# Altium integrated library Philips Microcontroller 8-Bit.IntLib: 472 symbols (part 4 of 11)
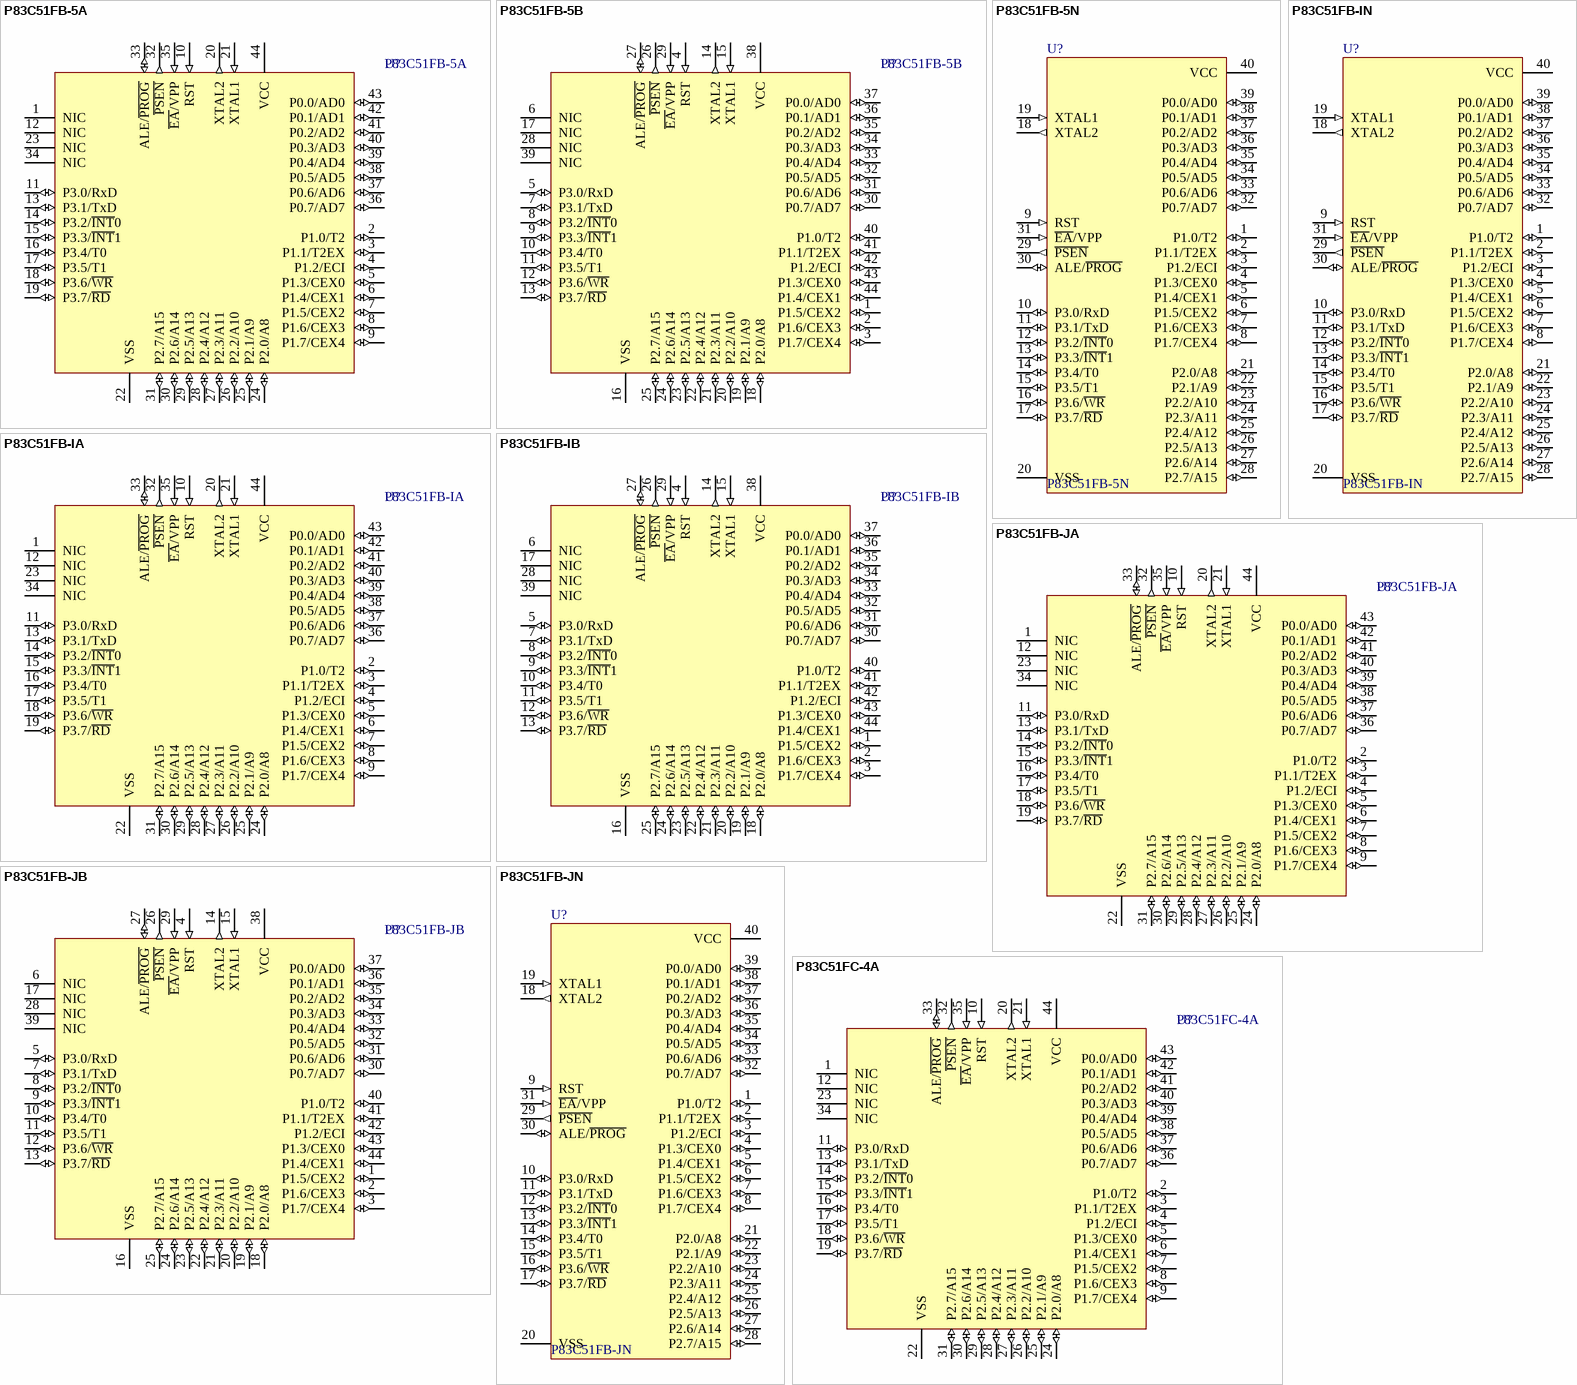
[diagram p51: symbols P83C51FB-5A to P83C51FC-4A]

## P83C51FB-JA
designator U?
80C51 8-Bit Microcontroller Family: 256 B RAM, 16 kB ROM, 5V, Low Power, High Speed
footprint SOT187-2_N (Leaded Chip Carrier, 44-Leads, Body 16.6x16.6mm, Pitch 1.27mm, IPC Medium Density)
footprint SOT187-2_L (Leaded Chip Carrier, 44-Leads, Body 16.6x16.6mm, Pitch 1.27mm, IPC High Density)
footprint SOT187-2_M (Leaded Chip Carrier, 44-Leads, Body 16.6x16.6mm, Pitch 1.27mm, IPC Low Density)
pins: 1 NIC, 2 P1.0/T2 (io), 3 P1.1/T2EX (io), 4 P1.2/ECI (io), 5 P1.3/CEX0 (io), 6 P1.4/CEX1 (io), 7 P1.5/CEX2 (io), 8 P1.6/CEX3 (io), 9 P1.7/CEX4 (io), 10 RST (in), 11 P3.0/RxD (io), 12 NIC, 13 P3.1/TxD (io), 14 P3.2/~{INT}0 (io), 15 P3.3/~{INT}1 (io), 16 P3.4/T0 (io), 17 P3.5/T1 (io), 18 P3.6/~{WR} (io), 19 P3.7/~{RD} (io), 20 XTAL2 (out), 21 XTAL1 (in), 22 VSS (power), 23 NIC, 24 P2.0/A8 (io), 25 P2.1/A9 (io), 26 P2.2/A10 (io), 27 P2.3/A11 (io), 28 P2.4/A12 (io), 29 P2.5/A13 (io), 30 P2.6/A14 (io), 31 P2.7/A15 (io), 32 ~{PSEN} (out), 33 ALE/~{PROG} (io), 34 NIC, 35 ~{EA}/VPP (in), 36 P0.7/AD7 (io), 37 P0.6/AD6 (io), 38 P0.5/AD5 (io), 39 P0.4/AD4 (io), 40 P0.3/AD3 (io), 41 P0.2/AD2 (io), 42 P0.1/AD1 (io), 43 P0.0/AD0 (io), 44 VCC (power)

## P83C51FB-JB
designator U?
80C51 8-Bit Microcontroller Family: 256 B RAM, 16 kB ROM, 5V, Low Power, High Speed
footprint SOT307-2_N (QFP, 44-Leads, Body 10x10mm, Pitch 0.8mm, IPC Medium Density)
footprint SOT307-2_L (QFP, 44-Leads, Body 10x10mm, Pitch 0.8mm, IPC High Density)
footprint SOT307-2_M (QFP, 44-Leads, Body 10x10mm, Pitch 0.8mm, IPC Low Density)
pins: 1 P1.5/CEX2 (io), 2 P1.6/CEX3 (io), 3 P1.7/CEX4 (io), 4 RST (in), 5 P3.0/RxD (io), 6 NIC, 7 P3.1/TxD (io), 8 P3.2/~{INT}0 (io), 9 P3.3/~{INT}1 (io), 10 P3.4/T0 (io), 11 P3.5/T1 (io), 12 P3.6/~{WR} (io), 13 P3.7/~{RD} (io), 14 XTAL2 (out), 15 XTAL1 (in), 16 VSS (power), 17 NIC, 18 P2.0/A8 (io), 19 P2.1/A9 (io), 20 P2.2/A10 (io), 21 P2.3/A11 (io), 22 P2.4/A12 (io), 23 P2.5/A13 (io), 24 P2.6/A14 (io), 25 P2.7/A15 (io), 26 ~{PSEN} (out), 27 ALE/~{PROG} (io), 28 NIC, 29 ~{EA}/VPP (in), 30 P0.7/AD7 (io), 31 P0.6/AD6 (io), 32 P0.5/AD5 (io), 33 P0.4/AD4 (io), 34 P0.3/AD3 (io), 35 P0.2/AD2 (io), 36 P0.1/AD1 (io), 37 P0.0/AD0 (io), 38 VCC (power), 39 NIC, 40 P1.0/T2 (io), 41 P1.1/T2EX (io), 42 P1.2/ECI (io), 43 P1.3/CEX0 (io), 44 P1.4/CEX1 (io)

## P83C51FB-JN
designator U?
80C51 8-Bit Microcontroller Family: 256 B RAM, 16 kB ROM, 5V, Low Power, High Speed
footprint SOT129-1 (DIP, Plastic; 40 Leads; Row Spacing 15.24 mm; Pitch 2.54 mm)
pins: 1 P1.0/T2 (io), 2 P1.1/T2EX (io), 3 P1.2/ECI (io), 4 P1.3/CEX0 (io), 5 P1.4/CEX1 (io), 6 P1.5/CEX2 (io), 7 P1.6/CEX3 (io), 8 P1.7/CEX4 (io), 9 RST (in), 10 P3.0/RxD (io), 11 P3.1/TxD (io), 12 P3.2/~{INT}0 (io), 13 P3.3/~{INT}1 (io), 14 P3.4/T0 (io), 15 P3.5/T1 (io), 16 P3.6/~{WR} (io), 17 P3.7/~{RD} (io), 18 XTAL2 (out), 19 XTAL1 (in), 20 VSS (power), 21 P2.0/A8 (io), 22 P2.1/A9 (io), 23 P2.2/A10 (io), 24 P2.3/A11 (io), 25 P2.4/A12 (io), 26 P2.5/A13 (io), 27 P2.6/A14 (io), 28 P2.7/A15 (io), 29 ~{PSEN} (out), 30 ALE/~{PROG} (io), 31 ~{EA}/VPP (in), 32 P0.7/AD7 (io), 33 P0.6/AD6 (io), 34 P0.5/AD5 (io), 35 P0.4/AD4 (io), 36 P0.3/AD3 (io), 37 P0.2/AD2 (io), 38 P0.1/AD1 (io), 39 P0.0/AD0 (io), 40 VCC (power)

## P83C51FC-4A
designator U?
80C51 8-Bit Microcontroller Family: 256 B RAM, 32 kB ROM, 2.7V-5.5V, Low Power, High Speed
footprint SOT187-2_N (Leaded Chip Carrier, 44-Leads, Body 16.6x16.6mm, Pitch 1.27mm, IPC Medium Density)
footprint SOT187-2_L (Leaded Chip Carrier, 44-Leads, Body 16.6x16.6mm, Pitch 1.27mm, IPC High Density)
footprint SOT187-2_M (Leaded Chip Carrier, 44-Leads, Body 16.6x16.6mm, Pitch 1.27mm, IPC Low Density)
pins: 1 NIC, 2 P1.0/T2 (io), 3 P1.1/T2EX (io), 4 P1.2/ECI (io), 5 P1.3/CEX0 (io), 6 P1.4/CEX1 (io), 7 P1.5/CEX2 (io), 8 P1.6/CEX3 (io), 9 P1.7/CEX4 (io), 10 RST (in), 11 P3.0/RxD (io), 12 NIC, 13 P3.1/TxD (io), 14 P3.2/~{INT}0 (io), 15 P3.3/~{INT}1 (io), 16 P3.4/T0 (io), 17 P3.5/T1 (io), 18 P3.6/~{WR} (io), 19 P3.7/~{RD} (io), 20 XTAL2 (out), 21 XTAL1 (in), 22 VSS (power), 23 NIC, 24 P2.0/A8 (io), 25 P2.1/A9 (io), 26 P2.2/A10 (io), 27 P2.3/A11 (io), 28 P2.4/A12 (io), 29 P2.5/A13 (io), 30 P2.6/A14 (io), 31 P2.7/A15 (io), 32 ~{PSEN} (out), 33 ALE/~{PROG} (io), 34 NIC, 35 ~{EA}/VPP (in), 36 P0.7/AD7 (io), 37 P0.6/AD6 (io), 38 P0.5/AD5 (io), 39 P0.4/AD4 (io), 40 P0.3/AD3 (io), 41 P0.2/AD2 (io), 42 P0.1/AD1 (io), 43 P0.0/AD0 (io), 44 VCC (power)

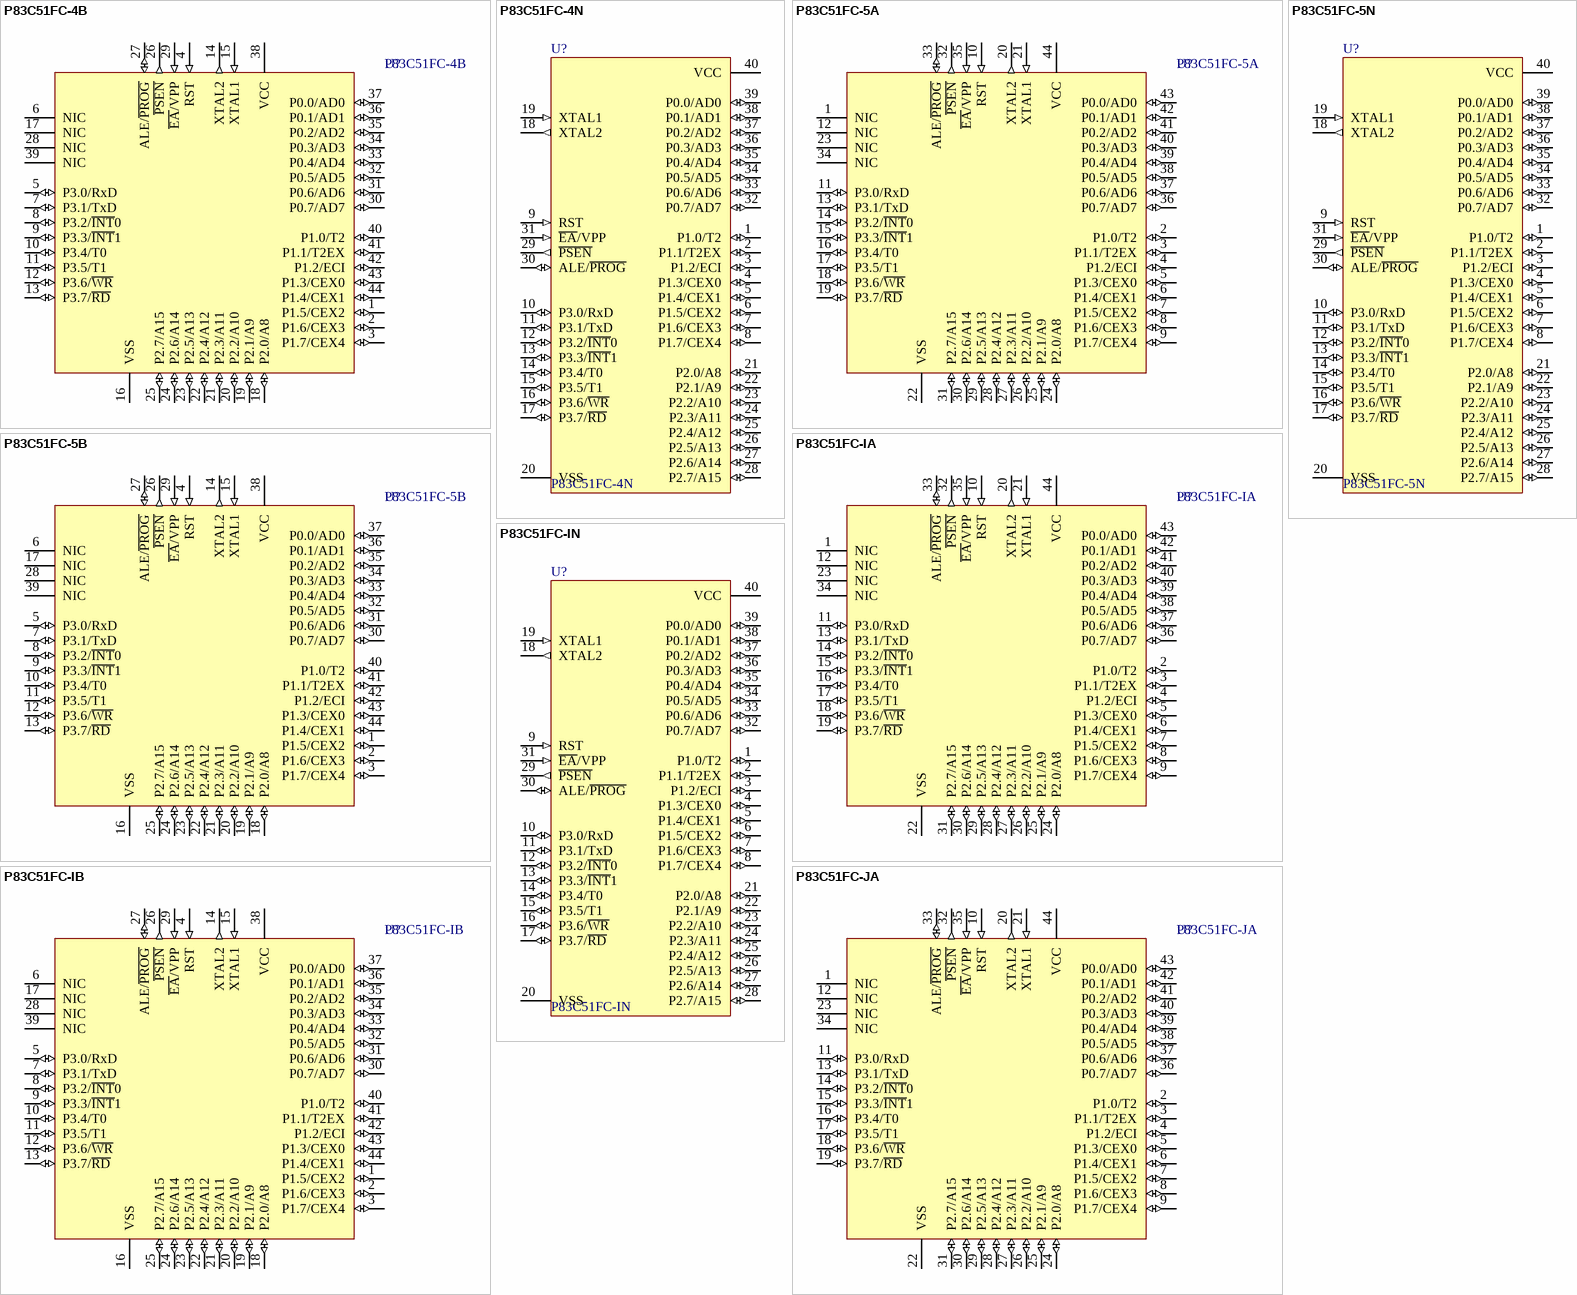
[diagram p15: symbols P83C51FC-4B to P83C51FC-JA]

## P83C51FC-4B
designator U?
80C51 8-Bit Microcontroller Family: 256 B RAM, 32 kB ROM, 2.7V-5.5V, Low Power, High Speed
footprint SOT307-2_N (QFP, 44-Leads, Body 10x10mm, Pitch 0.8mm, IPC Medium Density)
footprint SOT307-2_L (QFP, 44-Leads, Body 10x10mm, Pitch 0.8mm, IPC High Density)
footprint SOT307-2_M (QFP, 44-Leads, Body 10x10mm, Pitch 0.8mm, IPC Low Density)
pins: 1 P1.5/CEX2 (io), 2 P1.6/CEX3 (io), 3 P1.7/CEX4 (io), 4 RST (in), 5 P3.0/RxD (io), 6 NIC, 7 P3.1/TxD (io), 8 P3.2/~{INT}0 (io), 9 P3.3/~{INT}1 (io), 10 P3.4/T0 (io), 11 P3.5/T1 (io), 12 P3.6/~{WR} (io), 13 P3.7/~{RD} (io), 14 XTAL2 (out), 15 XTAL1 (in), 16 VSS (power), 17 NIC, 18 P2.0/A8 (io), 19 P2.1/A9 (io), 20 P2.2/A10 (io), 21 P2.3/A11 (io), 22 P2.4/A12 (io), 23 P2.5/A13 (io), 24 P2.6/A14 (io), 25 P2.7/A15 (io), 26 ~{PSEN} (out), 27 ALE/~{PROG} (io), 28 NIC, 29 ~{EA}/VPP (in), 30 P0.7/AD7 (io), 31 P0.6/AD6 (io), 32 P0.5/AD5 (io), 33 P0.4/AD4 (io), 34 P0.3/AD3 (io), 35 P0.2/AD2 (io), 36 P0.1/AD1 (io), 37 P0.0/AD0 (io), 38 VCC (power), 39 NIC, 40 P1.0/T2 (io), 41 P1.1/T2EX (io), 42 P1.2/ECI (io), 43 P1.3/CEX0 (io), 44 P1.4/CEX1 (io)

## P83C51FC-4N
designator U?
80C51 8-Bit Microcontroller Family: 256 B RAM, 32 kB ROM, 2.7V-5.5V, Low Power, High Speed
footprint SOT129-1 (DIP, Plastic; 40 Leads; Row Spacing 15.24 mm; Pitch 2.54 mm)
pins: 1 P1.0/T2 (io), 2 P1.1/T2EX (io), 3 P1.2/ECI (io), 4 P1.3/CEX0 (io), 5 P1.4/CEX1 (io), 6 P1.5/CEX2 (io), 7 P1.6/CEX3 (io), 8 P1.7/CEX4 (io), 9 RST (in), 10 P3.0/RxD (io), 11 P3.1/TxD (io), 12 P3.2/~{INT}0 (io), 13 P3.3/~{INT}1 (io), 14 P3.4/T0 (io), 15 P3.5/T1 (io), 16 P3.6/~{WR} (io), 17 P3.7/~{RD} (io), 18 XTAL2 (out), 19 XTAL1 (in), 20 VSS (power), 21 P2.0/A8 (io), 22 P2.1/A9 (io), 23 P2.2/A10 (io), 24 P2.3/A11 (io), 25 P2.4/A12 (io), 26 P2.5/A13 (io), 27 P2.6/A14 (io), 28 P2.7/A15 (io), 29 ~{PSEN} (out), 30 ALE/~{PROG} (io), 31 ~{EA}/VPP (in), 32 P0.7/AD7 (io), 33 P0.6/AD6 (io), 34 P0.5/AD5 (io), 35 P0.4/AD4 (io), 36 P0.3/AD3 (io), 37 P0.2/AD2 (io), 38 P0.1/AD1 (io), 39 P0.0/AD0 (io), 40 VCC (power)

## P83C51FC-5A
designator U?
80C51 8-Bit Microcontroller Family: 256 B RAM, 32 kB ROM, 2.7V-5.5V, Low Power, High Speed
footprint SOT187-2_N (Leaded Chip Carrier, 44-Leads, Body 16.6x16.6mm, Pitch 1.27mm, IPC Medium Density)
footprint SOT187-2_L (Leaded Chip Carrier, 44-Leads, Body 16.6x16.6mm, Pitch 1.27mm, IPC High Density)
footprint SOT187-2_M (Leaded Chip Carrier, 44-Leads, Body 16.6x16.6mm, Pitch 1.27mm, IPC Low Density)
pins: 1 NIC, 2 P1.0/T2 (io), 3 P1.1/T2EX (io), 4 P1.2/ECI (io), 5 P1.3/CEX0 (io), 6 P1.4/CEX1 (io), 7 P1.5/CEX2 (io), 8 P1.6/CEX3 (io), 9 P1.7/CEX4 (io), 10 RST (in), 11 P3.0/RxD (io), 12 NIC, 13 P3.1/TxD (io), 14 P3.2/~{INT}0 (io), 15 P3.3/~{INT}1 (io), 16 P3.4/T0 (io), 17 P3.5/T1 (io), 18 P3.6/~{WR} (io), 19 P3.7/~{RD} (io), 20 XTAL2 (out), 21 XTAL1 (in), 22 VSS (power), 23 NIC, 24 P2.0/A8 (io), 25 P2.1/A9 (io), 26 P2.2/A10 (io), 27 P2.3/A11 (io), 28 P2.4/A12 (io), 29 P2.5/A13 (io), 30 P2.6/A14 (io), 31 P2.7/A15 (io), 32 ~{PSEN} (out), 33 ALE/~{PROG} (io), 34 NIC, 35 ~{EA}/VPP (in), 36 P0.7/AD7 (io), 37 P0.6/AD6 (io), 38 P0.5/AD5 (io), 39 P0.4/AD4 (io), 40 P0.3/AD3 (io), 41 P0.2/AD2 (io), 42 P0.1/AD1 (io), 43 P0.0/AD0 (io), 44 VCC (power)

## P83C51FC-5B
designator U?
80C51 8-Bit Microcontroller Family: 256 B RAM, 32 kB ROM, 2.7V-5.5V, Low Power, High Speed
footprint SOT307-2_N (QFP, 44-Leads, Body 10x10mm, Pitch 0.8mm, IPC Medium Density)
footprint SOT307-2_L (QFP, 44-Leads, Body 10x10mm, Pitch 0.8mm, IPC High Density)
footprint SOT307-2_M (QFP, 44-Leads, Body 10x10mm, Pitch 0.8mm, IPC Low Density)
pins: 1 P1.5/CEX2 (io), 2 P1.6/CEX3 (io), 3 P1.7/CEX4 (io), 4 RST (in), 5 P3.0/RxD (io), 6 NIC, 7 P3.1/TxD (io), 8 P3.2/~{INT}0 (io), 9 P3.3/~{INT}1 (io), 10 P3.4/T0 (io), 11 P3.5/T1 (io), 12 P3.6/~{WR} (io), 13 P3.7/~{RD} (io), 14 XTAL2 (out), 15 XTAL1 (in), 16 VSS (power), 17 NIC, 18 P2.0/A8 (io), 19 P2.1/A9 (io), 20 P2.2/A10 (io), 21 P2.3/A11 (io), 22 P2.4/A12 (io), 23 P2.5/A13 (io), 24 P2.6/A14 (io), 25 P2.7/A15 (io), 26 ~{PSEN} (out), 27 ALE/~{PROG} (io), 28 NIC, 29 ~{EA}/VPP (in), 30 P0.7/AD7 (io), 31 P0.6/AD6 (io), 32 P0.5/AD5 (io), 33 P0.4/AD4 (io), 34 P0.3/AD3 (io), 35 P0.2/AD2 (io), 36 P0.1/AD1 (io), 37 P0.0/AD0 (io), 38 VCC (power), 39 NIC, 40 P1.0/T2 (io), 41 P1.1/T2EX (io), 42 P1.2/ECI (io), 43 P1.3/CEX0 (io), 44 P1.4/CEX1 (io)

## P83C51FC-5N
designator U?
80C51 8-Bit Microcontroller Family: 256 B RAM, 32 kB ROM, 2.7V-5.5V, Low Power, High Speed
footprint SOT129-1 (DIP, Plastic; 40 Leads; Row Spacing 15.24 mm; Pitch 2.54 mm)
pins: 1 P1.0/T2 (io), 2 P1.1/T2EX (io), 3 P1.2/ECI (io), 4 P1.3/CEX0 (io), 5 P1.4/CEX1 (io), 6 P1.5/CEX2 (io), 7 P1.6/CEX3 (io), 8 P1.7/CEX4 (io), 9 RST (in), 10 P3.0/RxD (io), 11 P3.1/TxD (io), 12 P3.2/~{INT}0 (io), 13 P3.3/~{INT}1 (io), 14 P3.4/T0 (io), 15 P3.5/T1 (io), 16 P3.6/~{WR} (io), 17 P3.7/~{RD} (io), 18 XTAL2 (out), 19 XTAL1 (in), 20 VSS (power), 21 P2.0/A8 (io), 22 P2.1/A9 (io), 23 P2.2/A10 (io), 24 P2.3/A11 (io), 25 P2.4/A12 (io), 26 P2.5/A13 (io), 27 P2.6/A14 (io), 28 P2.7/A15 (io), 29 ~{PSEN} (out), 30 ALE/~{PROG} (io), 31 ~{EA}/VPP (in), 32 P0.7/AD7 (io), 33 P0.6/AD6 (io), 34 P0.5/AD5 (io), 35 P0.4/AD4 (io), 36 P0.3/AD3 (io), 37 P0.2/AD2 (io), 38 P0.1/AD1 (io), 39 P0.0/AD0 (io), 40 VCC (power)

## P83C51FC-IA
designator U?
80C51 8-Bit Microcontroller Family: 256 B RAM, 32 kB ROM, 5V, Low Power, High Speed
footprint SOT187-2_N (Leaded Chip Carrier, 44-Leads, Body 16.6x16.6mm, Pitch 1.27mm, IPC Medium Density)
footprint SOT187-2_L (Leaded Chip Carrier, 44-Leads, Body 16.6x16.6mm, Pitch 1.27mm, IPC High Density)
footprint SOT187-2_M (Leaded Chip Carrier, 44-Leads, Body 16.6x16.6mm, Pitch 1.27mm, IPC Low Density)
pins: 1 NIC, 2 P1.0/T2 (io), 3 P1.1/T2EX (io), 4 P1.2/ECI (io), 5 P1.3/CEX0 (io), 6 P1.4/CEX1 (io), 7 P1.5/CEX2 (io), 8 P1.6/CEX3 (io), 9 P1.7/CEX4 (io), 10 RST (in), 11 P3.0/RxD (io), 12 NIC, 13 P3.1/TxD (io), 14 P3.2/~{INT}0 (io), 15 P3.3/~{INT}1 (io), 16 P3.4/T0 (io), 17 P3.5/T1 (io), 18 P3.6/~{WR} (io), 19 P3.7/~{RD} (io), 20 XTAL2 (out), 21 XTAL1 (in), 22 VSS (power), 23 NIC, 24 P2.0/A8 (io), 25 P2.1/A9 (io), 26 P2.2/A10 (io), 27 P2.3/A11 (io), 28 P2.4/A12 (io), 29 P2.5/A13 (io), 30 P2.6/A14 (io), 31 P2.7/A15 (io), 32 ~{PSEN} (out), 33 ALE/~{PROG} (io), 34 NIC, 35 ~{EA}/VPP (in), 36 P0.7/AD7 (io), 37 P0.6/AD6 (io), 38 P0.5/AD5 (io), 39 P0.4/AD4 (io), 40 P0.3/AD3 (io), 41 P0.2/AD2 (io), 42 P0.1/AD1 (io), 43 P0.0/AD0 (io), 44 VCC (power)

## P83C51FC-IB
designator U?
80C51 8-Bit Microcontroller Family: 256 B RAM, 32 kB ROM, 5V, Low Power, High Speed
footprint SOT307-2_N (QFP, 44-Leads, Body 10x10mm, Pitch 0.8mm, IPC Medium Density)
footprint SOT307-2_L (QFP, 44-Leads, Body 10x10mm, Pitch 0.8mm, IPC High Density)
footprint SOT307-2_M (QFP, 44-Leads, Body 10x10mm, Pitch 0.8mm, IPC Low Density)
pins: 1 P1.5/CEX2 (io), 2 P1.6/CEX3 (io), 3 P1.7/CEX4 (io), 4 RST (in), 5 P3.0/RxD (io), 6 NIC, 7 P3.1/TxD (io), 8 P3.2/~{INT}0 (io), 9 P3.3/~{INT}1 (io), 10 P3.4/T0 (io), 11 P3.5/T1 (io), 12 P3.6/~{WR} (io), 13 P3.7/~{RD} (io), 14 XTAL2 (out), 15 XTAL1 (in), 16 VSS (power), 17 NIC, 18 P2.0/A8 (io), 19 P2.1/A9 (io), 20 P2.2/A10 (io), 21 P2.3/A11 (io), 22 P2.4/A12 (io), 23 P2.5/A13 (io), 24 P2.6/A14 (io), 25 P2.7/A15 (io), 26 ~{PSEN} (out), 27 ALE/~{PROG} (io), 28 NIC, 29 ~{EA}/VPP (in), 30 P0.7/AD7 (io), 31 P0.6/AD6 (io), 32 P0.5/AD5 (io), 33 P0.4/AD4 (io), 34 P0.3/AD3 (io), 35 P0.2/AD2 (io), 36 P0.1/AD1 (io), 37 P0.0/AD0 (io), 38 VCC (power), 39 NIC, 40 P1.0/T2 (io), 41 P1.1/T2EX (io), 42 P1.2/ECI (io), 43 P1.3/CEX0 (io), 44 P1.4/CEX1 (io)

## P83C51FC-IN
designator U?
80C51 8-Bit Microcontroller Family: 256 B RAM, 32 kB ROM, 5V, Low Power, High Speed
footprint SOT129-1 (DIP, Plastic; 40 Leads; Row Spacing 15.24 mm; Pitch 2.54 mm)
pins: 1 P1.0/T2 (io), 2 P1.1/T2EX (io), 3 P1.2/ECI (io), 4 P1.3/CEX0 (io), 5 P1.4/CEX1 (io), 6 P1.5/CEX2 (io), 7 P1.6/CEX3 (io), 8 P1.7/CEX4 (io), 9 RST (in), 10 P3.0/RxD (io), 11 P3.1/TxD (io), 12 P3.2/~{INT}0 (io), 13 P3.3/~{INT}1 (io), 14 P3.4/T0 (io), 15 P3.5/T1 (io), 16 P3.6/~{WR} (io), 17 P3.7/~{RD} (io), 18 XTAL2 (out), 19 XTAL1 (in), 20 VSS (power), 21 P2.0/A8 (io), 22 P2.1/A9 (io), 23 P2.2/A10 (io), 24 P2.3/A11 (io), 25 P2.4/A12 (io), 26 P2.5/A13 (io), 27 P2.6/A14 (io), 28 P2.7/A15 (io), 29 ~{PSEN} (out), 30 ALE/~{PROG} (io), 31 ~{EA}/VPP (in), 32 P0.7/AD7 (io), 33 P0.6/AD6 (io), 34 P0.5/AD5 (io), 35 P0.4/AD4 (io), 36 P0.3/AD3 (io), 37 P0.2/AD2 (io), 38 P0.1/AD1 (io), 39 P0.0/AD0 (io), 40 VCC (power)

## P83C51FC-JA
designator U?
80C51 8-Bit Microcontroller Family: 256 B RAM, 32 kB ROM, 5V, Low Power, High Speed
footprint SOT187-2_N (Leaded Chip Carrier, 44-Leads, Body 16.6x16.6mm, Pitch 1.27mm, IPC Medium Density)
footprint SOT187-2_L (Leaded Chip Carrier, 44-Leads, Body 16.6x16.6mm, Pitch 1.27mm, IPC High Density)
footprint SOT187-2_M (Leaded Chip Carrier, 44-Leads, Body 16.6x16.6mm, Pitch 1.27mm, IPC Low Density)
pins: 1 NIC, 2 P1.0/T2 (io), 3 P1.1/T2EX (io), 4 P1.2/ECI (io), 5 P1.3/CEX0 (io), 6 P1.4/CEX1 (io), 7 P1.5/CEX2 (io), 8 P1.6/CEX3 (io), 9 P1.7/CEX4 (io), 10 RST (in), 11 P3.0/RxD (io), 12 NIC, 13 P3.1/TxD (io), 14 P3.2/~{INT}0 (io), 15 P3.3/~{INT}1 (io), 16 P3.4/T0 (io), 17 P3.5/T1 (io), 18 P3.6/~{WR} (io), 19 P3.7/~{RD} (io), 20 XTAL2 (out), 21 XTAL1 (in), 22 VSS (power), 23 NIC, 24 P2.0/A8 (io), 25 P2.1/A9 (io), 26 P2.2/A10 (io), 27 P2.3/A11 (io), 28 P2.4/A12 (io), 29 P2.5/A13 (io), 30 P2.6/A14 (io), 31 P2.7/A15 (io), 32 ~{PSEN} (out), 33 ALE/~{PROG} (io), 34 NIC, 35 ~{EA}/VPP (in), 36 P0.7/AD7 (io), 37 P0.6/AD6 (io), 38 P0.5/AD5 (io), 39 P0.4/AD4 (io), 40 P0.3/AD3 (io), 41 P0.2/AD2 (io), 42 P0.1/AD1 (io), 43 P0.0/AD0 (io), 44 VCC (power)

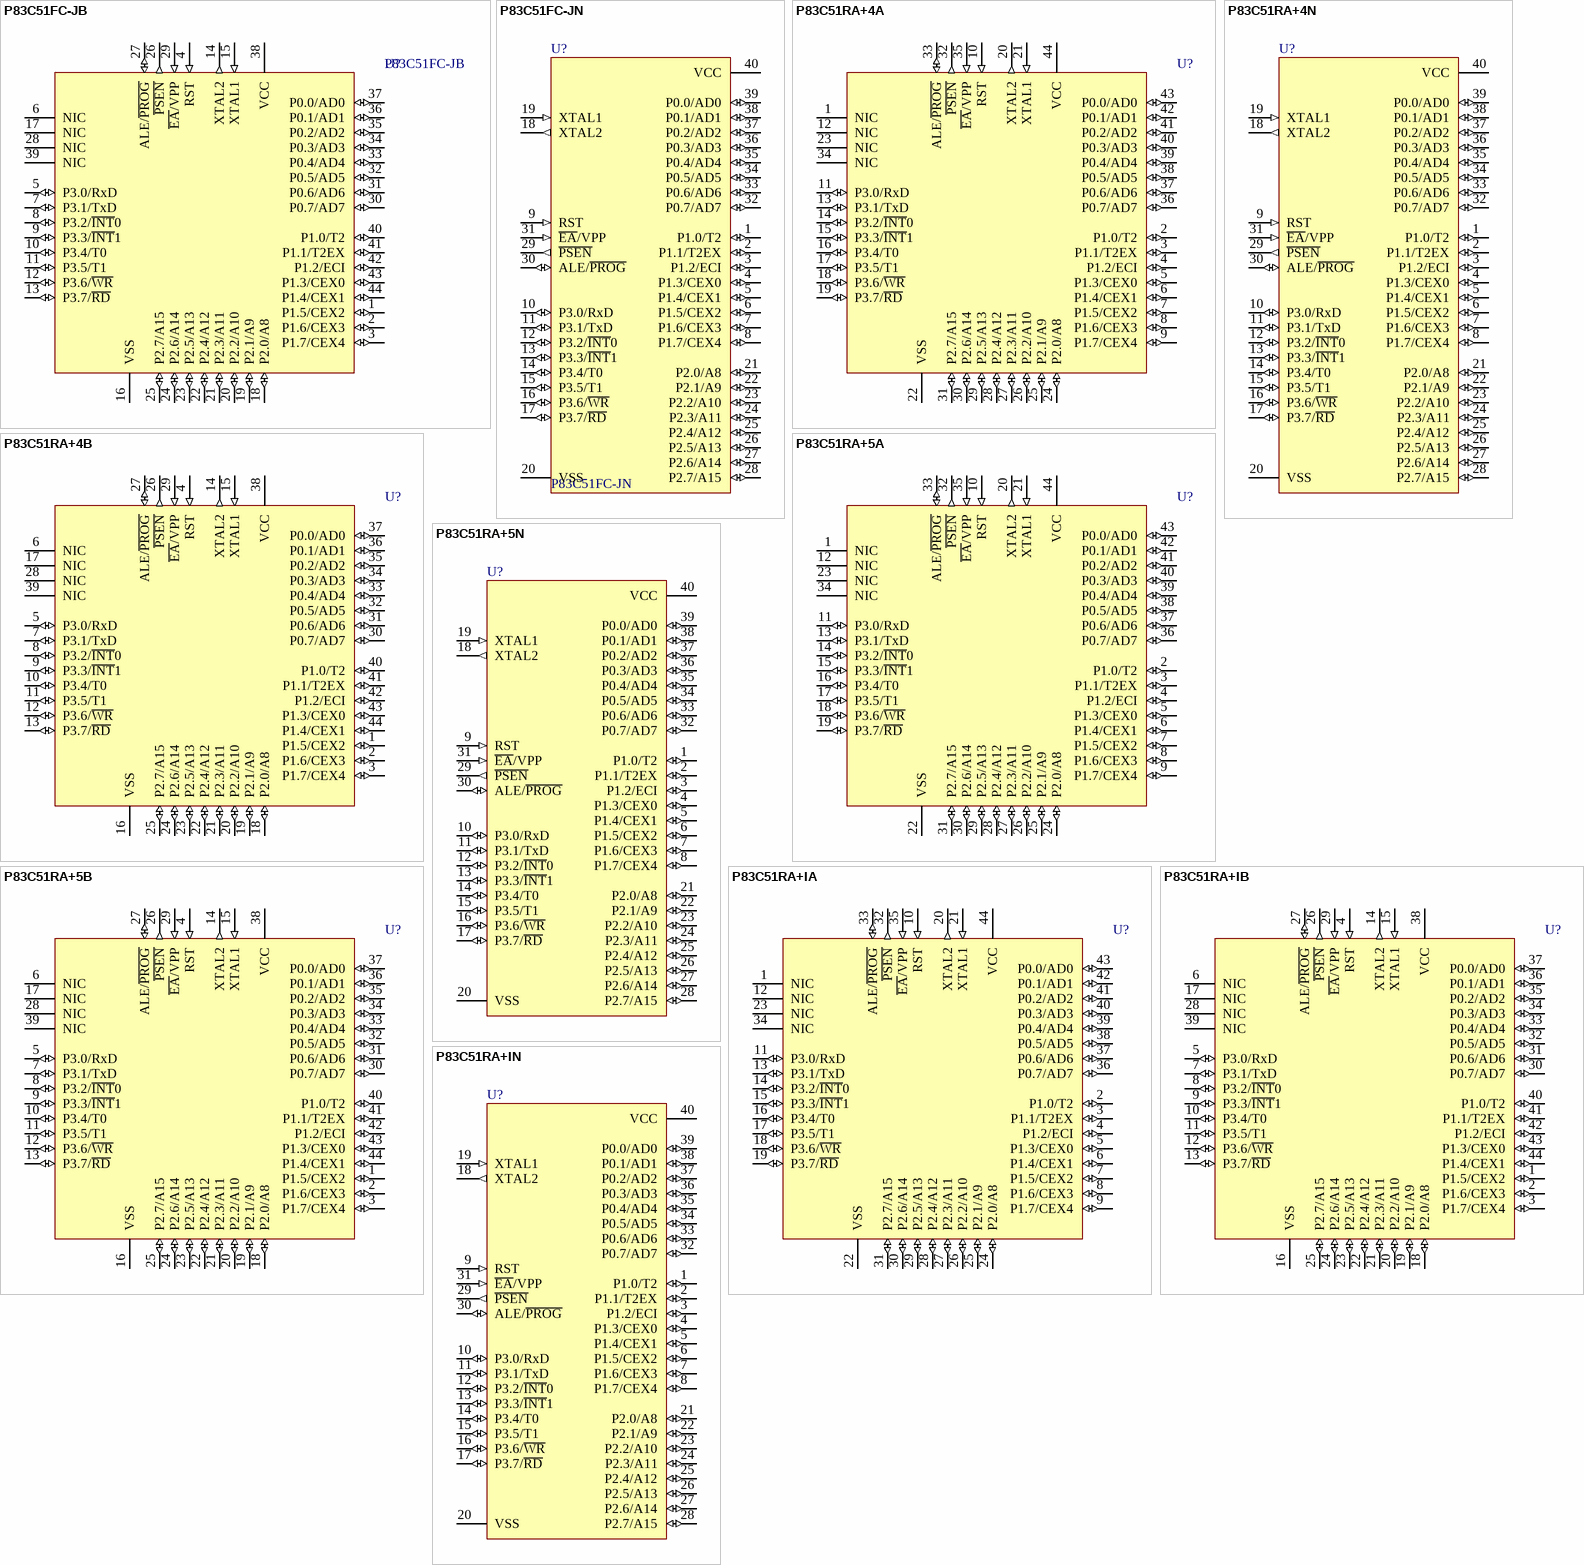
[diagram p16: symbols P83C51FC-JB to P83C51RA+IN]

## P83C51FC-JB
designator U?
80C51 8-Bit Microcontroller Family: 256 B RAM, 32 kB ROM, 5V, Low Power, High Speed
footprint SOT307-2_N (QFP, 44-Leads, Body 10x10mm, Pitch 0.8mm, IPC Medium Density)
footprint SOT307-2_L (QFP, 44-Leads, Body 10x10mm, Pitch 0.8mm, IPC High Density)
footprint SOT307-2_M (QFP, 44-Leads, Body 10x10mm, Pitch 0.8mm, IPC Low Density)
pins: 1 P1.5/CEX2 (io), 2 P1.6/CEX3 (io), 3 P1.7/CEX4 (io), 4 RST (in), 5 P3.0/RxD (io), 6 NIC, 7 P3.1/TxD (io), 8 P3.2/~{INT}0 (io), 9 P3.3/~{INT}1 (io), 10 P3.4/T0 (io), 11 P3.5/T1 (io), 12 P3.6/~{WR} (io), 13 P3.7/~{RD} (io), 14 XTAL2 (out), 15 XTAL1 (in), 16 VSS (power), 17 NIC, 18 P2.0/A8 (io), 19 P2.1/A9 (io), 20 P2.2/A10 (io), 21 P2.3/A11 (io), 22 P2.4/A12 (io), 23 P2.5/A13 (io), 24 P2.6/A14 (io), 25 P2.7/A15 (io), 26 ~{PSEN} (out), 27 ALE/~{PROG} (io), 28 NIC, 29 ~{EA}/VPP (in), 30 P0.7/AD7 (io), 31 P0.6/AD6 (io), 32 P0.5/AD5 (io), 33 P0.4/AD4 (io), 34 P0.3/AD3 (io), 35 P0.2/AD2 (io), 36 P0.1/AD1 (io), 37 P0.0/AD0 (io), 38 VCC (power), 39 NIC, 40 P1.0/T2 (io), 41 P1.1/T2EX (io), 42 P1.2/ECI (io), 43 P1.3/CEX0 (io), 44 P1.4/CEX1 (io)

## P83C51FC-JN
designator U?
80C51 8-Bit Microcontroller Family: 256 B RAM, 32 kB ROM, 5V, Low Power, High Speed
footprint SOT129-1 (DIP, Plastic; 40 Leads; Row Spacing 15.24 mm; Pitch 2.54 mm)
pins: 1 P1.0/T2 (io), 2 P1.1/T2EX (io), 3 P1.2/ECI (io), 4 P1.3/CEX0 (io), 5 P1.4/CEX1 (io), 6 P1.5/CEX2 (io), 7 P1.6/CEX3 (io), 8 P1.7/CEX4 (io), 9 RST (in), 10 P3.0/RxD (io), 11 P3.1/TxD (io), 12 P3.2/~{INT}0 (io), 13 P3.3/~{INT}1 (io), 14 P3.4/T0 (io), 15 P3.5/T1 (io), 16 P3.6/~{WR} (io), 17 P3.7/~{RD} (io), 18 XTAL2 (out), 19 XTAL1 (in), 20 VSS (power), 21 P2.0/A8 (io), 22 P2.1/A9 (io), 23 P2.2/A10 (io), 24 P2.3/A11 (io), 25 P2.4/A12 (io), 26 P2.5/A13 (io), 27 P2.6/A14 (io), 28 P2.7/A15 (io), 29 ~{PSEN} (out), 30 ALE/~{PROG} (io), 31 ~{EA}/VPP (in), 32 P0.7/AD7 (io), 33 P0.6/AD6 (io), 34 P0.5/AD5 (io), 35 P0.4/AD4 (io), 36 P0.3/AD3 (io), 37 P0.2/AD2 (io), 38 P0.1/AD1 (io), 39 P0.0/AD0 (io), 40 VCC (power)

## P83C51RA+4A
designator U?
80C51 8-Bit Microcontroller Family: 512 B RAM, 8 kB ROM, 2.7V-5.5V, Low Power, High Speed
footprint SOT187-2_N (Leaded Chip Carrier, 44-Leads, Body 16.6x16.6mm, Pitch 1.27mm, IPC Medium Density)
footprint SOT187-2_L (Leaded Chip Carrier, 44-Leads, Body 16.6x16.6mm, Pitch 1.27mm, IPC High Density)
footprint SOT187-2_M (Leaded Chip Carrier, 44-Leads, Body 16.6x16.6mm, Pitch 1.27mm, IPC Low Density)
pins: 1 NIC, 2 P1.0/T2 (io), 3 P1.1/T2EX (io), 4 P1.2/ECI (io), 5 P1.3/CEX0 (io), 6 P1.4/CEX1 (io), 7 P1.5/CEX2 (io), 8 P1.6/CEX3 (io), 9 P1.7/CEX4 (io), 10 RST (in), 11 P3.0/RxD (io), 12 NIC, 13 P3.1/TxD (io), 14 P3.2/~{INT}0 (io), 15 P3.3/~{INT}1 (io), 16 P3.4/T0 (io), 17 P3.5/T1 (io), 18 P3.6/~{WR} (io), 19 P3.7/~{RD} (io), 20 XTAL2 (out), 21 XTAL1 (in), 22 VSS (power), 23 NIC, 24 P2.0/A8 (io), 25 P2.1/A9 (io), 26 P2.2/A10 (io), 27 P2.3/A11 (io), 28 P2.4/A12 (io), 29 P2.5/A13 (io), 30 P2.6/A14 (io), 31 P2.7/A15 (io), 32 ~{PSEN} (out), 33 ALE/~{PROG} (io), 34 NIC, 35 ~{EA}/VPP (in), 36 P0.7/AD7 (io), 37 P0.6/AD6 (io), 38 P0.5/AD5 (io), 39 P0.4/AD4 (io), 40 P0.3/AD3 (io), 41 P0.2/AD2 (io), 42 P0.1/AD1 (io), 43 P0.0/AD0 (io), 44 VCC (power)

## P83C51RA+4B
designator U?
80C51 8-Bit Microcontroller Family: 512 B RAM, 8 kB ROM, 2.7V-5.5V, Low Power, High Speed
footprint SOT307-2_N (QFP, 44-Leads, Body 10x10mm, Pitch 0.8mm, IPC Medium Density)
footprint SOT307-2_L (QFP, 44-Leads, Body 10x10mm, Pitch 0.8mm, IPC High Density)
footprint SOT307-2_M (QFP, 44-Leads, Body 10x10mm, Pitch 0.8mm, IPC Low Density)
pins: 1 P1.5/CEX2 (io), 2 P1.6/CEX3 (io), 3 P1.7/CEX4 (io), 4 RST (in), 5 P3.0/RxD (io), 6 NIC, 7 P3.1/TxD (io), 8 P3.2/~{INT}0 (io), 9 P3.3/~{INT}1 (io), 10 P3.4/T0 (io), 11 P3.5/T1 (io), 12 P3.6/~{WR} (io), 13 P3.7/~{RD} (io), 14 XTAL2 (out), 15 XTAL1 (in), 16 VSS (power), 17 NIC, 18 P2.0/A8 (io), 19 P2.1/A9 (io), 20 P2.2/A10 (io), 21 P2.3/A11 (io), 22 P2.4/A12 (io), 23 P2.5/A13 (io), 24 P2.6/A14 (io), 25 P2.7/A15 (io), 26 ~{PSEN} (out), 27 ALE/~{PROG} (io), 28 NIC, 29 ~{EA}/VPP (in), 30 P0.7/AD7 (io), 31 P0.6/AD6 (io), 32 P0.5/AD5 (io), 33 P0.4/AD4 (io), 34 P0.3/AD3 (io), 35 P0.2/AD2 (io), 36 P0.1/AD1 (io), 37 P0.0/AD0 (io), 38 VCC (power), 39 NIC, 40 P1.0/T2 (io), 41 P1.1/T2EX (io), 42 P1.2/ECI (io), 43 P1.3/CEX0 (io), 44 P1.4/CEX1 (io)

## P83C51RA+4N
designator U?
80C51 8-Bit Microcontroller Family: 512 B RAM, 8 kB ROM, 2.7V-5.5V, Low Power, High Speed
footprint SOT129-1 (DIP, Plastic; 40 Leads; Row Spacing 15.24 mm; Pitch 2.54 mm)
pins: 1 P1.0/T2 (io), 2 P1.1/T2EX (io), 3 P1.2/ECI (io), 4 P1.3/CEX0 (io), 5 P1.4/CEX1 (io), 6 P1.5/CEX2 (io), 7 P1.6/CEX3 (io), 8 P1.7/CEX4 (io), 9 RST (in), 10 P3.0/RxD (io), 11 P3.1/TxD (io), 12 P3.2/~{INT}0 (io), 13 P3.3/~{INT}1 (io), 14 P3.4/T0 (io), 15 P3.5/T1 (io), 16 P3.6/~{WR} (io), 17 P3.7/~{RD} (io), 18 XTAL2 (out), 19 XTAL1 (in), 20 VSS (power), 21 P2.0/A8 (io), 22 P2.1/A9 (io), 23 P2.2/A10 (io), 24 P2.3/A11 (io), 25 P2.4/A12 (io), 26 P2.5/A13 (io), 27 P2.6/A14 (io), 28 P2.7/A15 (io), 29 ~{PSEN} (out), 30 ALE/~{PROG} (io), 31 ~{EA}/VPP (in), 32 P0.7/AD7 (io), 33 P0.6/AD6 (io), 34 P0.5/AD5 (io), 35 P0.4/AD4 (io), 36 P0.3/AD3 (io), 37 P0.2/AD2 (io), 38 P0.1/AD1 (io), 39 P0.0/AD0 (io), 40 VCC (power)

## P83C51RA+5A
designator U?
80C51 8-Bit Microcontroller Family: 512 B RAM, 8 kB ROM, 2.7V-5.5V, Low Power, High Speed
footprint SOT187-2_N (Leaded Chip Carrier, 44-Leads, Body 16.6x16.6mm, Pitch 1.27mm, IPC Medium Density)
footprint SOT187-2_L (Leaded Chip Carrier, 44-Leads, Body 16.6x16.6mm, Pitch 1.27mm, IPC High Density)
footprint SOT187-2_M (Leaded Chip Carrier, 44-Leads, Body 16.6x16.6mm, Pitch 1.27mm, IPC Low Density)
pins: 1 NIC, 2 P1.0/T2 (io), 3 P1.1/T2EX (io), 4 P1.2/ECI (io), 5 P1.3/CEX0 (io), 6 P1.4/CEX1 (io), 7 P1.5/CEX2 (io), 8 P1.6/CEX3 (io), 9 P1.7/CEX4 (io), 10 RST (in), 11 P3.0/RxD (io), 12 NIC, 13 P3.1/TxD (io), 14 P3.2/~{INT}0 (io), 15 P3.3/~{INT}1 (io), 16 P3.4/T0 (io), 17 P3.5/T1 (io), 18 P3.6/~{WR} (io), 19 P3.7/~{RD} (io), 20 XTAL2 (out), 21 XTAL1 (in), 22 VSS (power), 23 NIC, 24 P2.0/A8 (io), 25 P2.1/A9 (io), 26 P2.2/A10 (io), 27 P2.3/A11 (io), 28 P2.4/A12 (io), 29 P2.5/A13 (io), 30 P2.6/A14 (io), 31 P2.7/A15 (io), 32 ~{PSEN} (out), 33 ALE/~{PROG} (io), 34 NIC, 35 ~{EA}/VPP (in), 36 P0.7/AD7 (io), 37 P0.6/AD6 (io), 38 P0.5/AD5 (io), 39 P0.4/AD4 (io), 40 P0.3/AD3 (io), 41 P0.2/AD2 (io), 42 P0.1/AD1 (io), 43 P0.0/AD0 (io), 44 VCC (power)

## P83C51RA+5B
designator U?
80C51 8-Bit Microcontroller Family: 512 B RAM, 8 kB ROM, 2.7V-5.5V, Low Power, High Speed
footprint SOT307-2_N (QFP, 44-Leads, Body 10x10mm, Pitch 0.8mm, IPC Medium Density)
footprint SOT307-2_L (QFP, 44-Leads, Body 10x10mm, Pitch 0.8mm, IPC High Density)
footprint SOT307-2_M (QFP, 44-Leads, Body 10x10mm, Pitch 0.8mm, IPC Low Density)
pins: 1 P1.5/CEX2 (io), 2 P1.6/CEX3 (io), 3 P1.7/CEX4 (io), 4 RST (in), 5 P3.0/RxD (io), 6 NIC, 7 P3.1/TxD (io), 8 P3.2/~{INT}0 (io), 9 P3.3/~{INT}1 (io), 10 P3.4/T0 (io), 11 P3.5/T1 (io), 12 P3.6/~{WR} (io), 13 P3.7/~{RD} (io), 14 XTAL2 (out), 15 XTAL1 (in), 16 VSS (power), 17 NIC, 18 P2.0/A8 (io), 19 P2.1/A9 (io), 20 P2.2/A10 (io), 21 P2.3/A11 (io), 22 P2.4/A12 (io), 23 P2.5/A13 (io), 24 P2.6/A14 (io), 25 P2.7/A15 (io), 26 ~{PSEN} (out), 27 ALE/~{PROG} (io), 28 NIC, 29 ~{EA}/VPP (in), 30 P0.7/AD7 (io), 31 P0.6/AD6 (io), 32 P0.5/AD5 (io), 33 P0.4/AD4 (io), 34 P0.3/AD3 (io), 35 P0.2/AD2 (io), 36 P0.1/AD1 (io), 37 P0.0/AD0 (io), 38 VCC (power), 39 NIC, 40 P1.0/T2 (io), 41 P1.1/T2EX (io), 42 P1.2/ECI (io), 43 P1.3/CEX0 (io), 44 P1.4/CEX1 (io)

## P83C51RA+5N
designator U?
80C51 8-Bit Microcontroller Family: 512 B RAM, 8 kB ROM, 2.7V-5.5V, Low Power, High Speed
footprint SOT129-1 (DIP, Plastic; 40 Leads; Row Spacing 15.24 mm; Pitch 2.54 mm)
pins: 1 P1.0/T2 (io), 2 P1.1/T2EX (io), 3 P1.2/ECI (io), 4 P1.3/CEX0 (io), 5 P1.4/CEX1 (io), 6 P1.5/CEX2 (io), 7 P1.6/CEX3 (io), 8 P1.7/CEX4 (io), 9 RST (in), 10 P3.0/RxD (io), 11 P3.1/TxD (io), 12 P3.2/~{INT}0 (io), 13 P3.3/~{INT}1 (io), 14 P3.4/T0 (io), 15 P3.5/T1 (io), 16 P3.6/~{WR} (io), 17 P3.7/~{RD} (io), 18 XTAL2 (out), 19 XTAL1 (in), 20 VSS (power), 21 P2.0/A8 (io), 22 P2.1/A9 (io), 23 P2.2/A10 (io), 24 P2.3/A11 (io), 25 P2.4/A12 (io), 26 P2.5/A13 (io), 27 P2.6/A14 (io), 28 P2.7/A15 (io), 29 ~{PSEN} (out), 30 ALE/~{PROG} (io), 31 ~{EA}/VPP (in), 32 P0.7/AD7 (io), 33 P0.6/AD6 (io), 34 P0.5/AD5 (io), 35 P0.4/AD4 (io), 36 P0.3/AD3 (io), 37 P0.2/AD2 (io), 38 P0.1/AD1 (io), 39 P0.0/AD0 (io), 40 VCC (power)

## P83C51RA+IA
designator U?
80C51 8-Bit Microcontroller Family: 512 B RAM, 8 kB ROM, 5V, Low Power, High Speed
footprint SOT187-2_N (Leaded Chip Carrier, 44-Leads, Body 16.6x16.6mm, Pitch 1.27mm, IPC Medium Density)
footprint SOT187-2_L (Leaded Chip Carrier, 44-Leads, Body 16.6x16.6mm, Pitch 1.27mm, IPC High Density)
footprint SOT187-2_M (Leaded Chip Carrier, 44-Leads, Body 16.6x16.6mm, Pitch 1.27mm, IPC Low Density)
pins: 1 NIC, 2 P1.0/T2 (io), 3 P1.1/T2EX (io), 4 P1.2/ECI (io), 5 P1.3/CEX0 (io), 6 P1.4/CEX1 (io), 7 P1.5/CEX2 (io), 8 P1.6/CEX3 (io), 9 P1.7/CEX4 (io), 10 RST (in), 11 P3.0/RxD (io), 12 NIC, 13 P3.1/TxD (io), 14 P3.2/~{INT}0 (io), 15 P3.3/~{INT}1 (io), 16 P3.4/T0 (io), 17 P3.5/T1 (io), 18 P3.6/~{WR} (io), 19 P3.7/~{RD} (io), 20 XTAL2 (out), 21 XTAL1 (in), 22 VSS (power), 23 NIC, 24 P2.0/A8 (io), 25 P2.1/A9 (io), 26 P2.2/A10 (io), 27 P2.3/A11 (io), 28 P2.4/A12 (io), 29 P2.5/A13 (io), 30 P2.6/A14 (io), 31 P2.7/A15 (io), 32 ~{PSEN} (out), 33 ALE/~{PROG} (io), 34 NIC, 35 ~{EA}/VPP (in), 36 P0.7/AD7 (io), 37 P0.6/AD6 (io), 38 P0.5/AD5 (io), 39 P0.4/AD4 (io), 40 P0.3/AD3 (io), 41 P0.2/AD2 (io), 42 P0.1/AD1 (io), 43 P0.0/AD0 (io), 44 VCC (power)

## P83C51RA+IB
designator U?
80C51 8-Bit Microcontroller Family: 512 B RAM, 8 kB ROM, 5V, Low Power, High Speed
footprint SOT307-2_N (QFP, 44-Leads, Body 10x10mm, Pitch 0.8mm, IPC Medium Density)
footprint SOT307-2_L (QFP, 44-Leads, Body 10x10mm, Pitch 0.8mm, IPC High Density)
footprint SOT307-2_M (QFP, 44-Leads, Body 10x10mm, Pitch 0.8mm, IPC Low Density)
pins: 1 P1.5/CEX2 (io), 2 P1.6/CEX3 (io), 3 P1.7/CEX4 (io), 4 RST (in), 5 P3.0/RxD (io), 6 NIC, 7 P3.1/TxD (io), 8 P3.2/~{INT}0 (io), 9 P3.3/~{INT}1 (io), 10 P3.4/T0 (io), 11 P3.5/T1 (io), 12 P3.6/~{WR} (io), 13 P3.7/~{RD} (io), 14 XTAL2 (out), 15 XTAL1 (in), 16 VSS (power), 17 NIC, 18 P2.0/A8 (io), 19 P2.1/A9 (io), 20 P2.2/A10 (io), 21 P2.3/A11 (io), 22 P2.4/A12 (io), 23 P2.5/A13 (io), 24 P2.6/A14 (io), 25 P2.7/A15 (io), 26 ~{PSEN} (out), 27 ALE/~{PROG} (io), 28 NIC, 29 ~{EA}/VPP (in), 30 P0.7/AD7 (io), 31 P0.6/AD6 (io), 32 P0.5/AD5 (io), 33 P0.4/AD4 (io), 34 P0.3/AD3 (io), 35 P0.2/AD2 (io), 36 P0.1/AD1 (io), 37 P0.0/AD0 (io), 38 VCC (power), 39 NIC, 40 P1.0/T2 (io), 41 P1.1/T2EX (io), 42 P1.2/ECI (io), 43 P1.3/CEX0 (io), 44 P1.4/CEX1 (io)

## P83C51RA+IN
designator U?
80C51 8-Bit Microcontroller Family: 512 B RAM, 8 kB ROM, 5V, Low Power, High Speed
footprint SOT129-1 (DIP, Plastic; 40 Leads; Row Spacing 15.24 mm; Pitch 2.54 mm)
pins: 1 P1.0/T2 (io), 2 P1.1/T2EX (io), 3 P1.2/ECI (io), 4 P1.3/CEX0 (io), 5 P1.4/CEX1 (io), 6 P1.5/CEX2 (io), 7 P1.6/CEX3 (io), 8 P1.7/CEX4 (io), 9 RST (in), 10 P3.0/RxD (io), 11 P3.1/TxD (io), 12 P3.2/~{INT}0 (io), 13 P3.3/~{INT}1 (io), 14 P3.4/T0 (io), 15 P3.5/T1 (io), 16 P3.6/~{WR} (io), 17 P3.7/~{RD} (io), 18 XTAL2 (out), 19 XTAL1 (in), 20 VSS (power), 21 P2.0/A8 (io), 22 P2.1/A9 (io), 23 P2.2/A10 (io), 24 P2.3/A11 (io), 25 P2.4/A12 (io), 26 P2.5/A13 (io), 27 P2.6/A14 (io), 28 P2.7/A15 (io), 29 ~{PSEN} (out), 30 ALE/~{PROG} (io), 31 ~{EA}/VPP (in), 32 P0.7/AD7 (io), 33 P0.6/AD6 (io), 34 P0.5/AD5 (io), 35 P0.4/AD4 (io), 36 P0.3/AD3 (io), 37 P0.2/AD2 (io), 38 P0.1/AD1 (io), 39 P0.0/AD0 (io), 40 VCC (power)

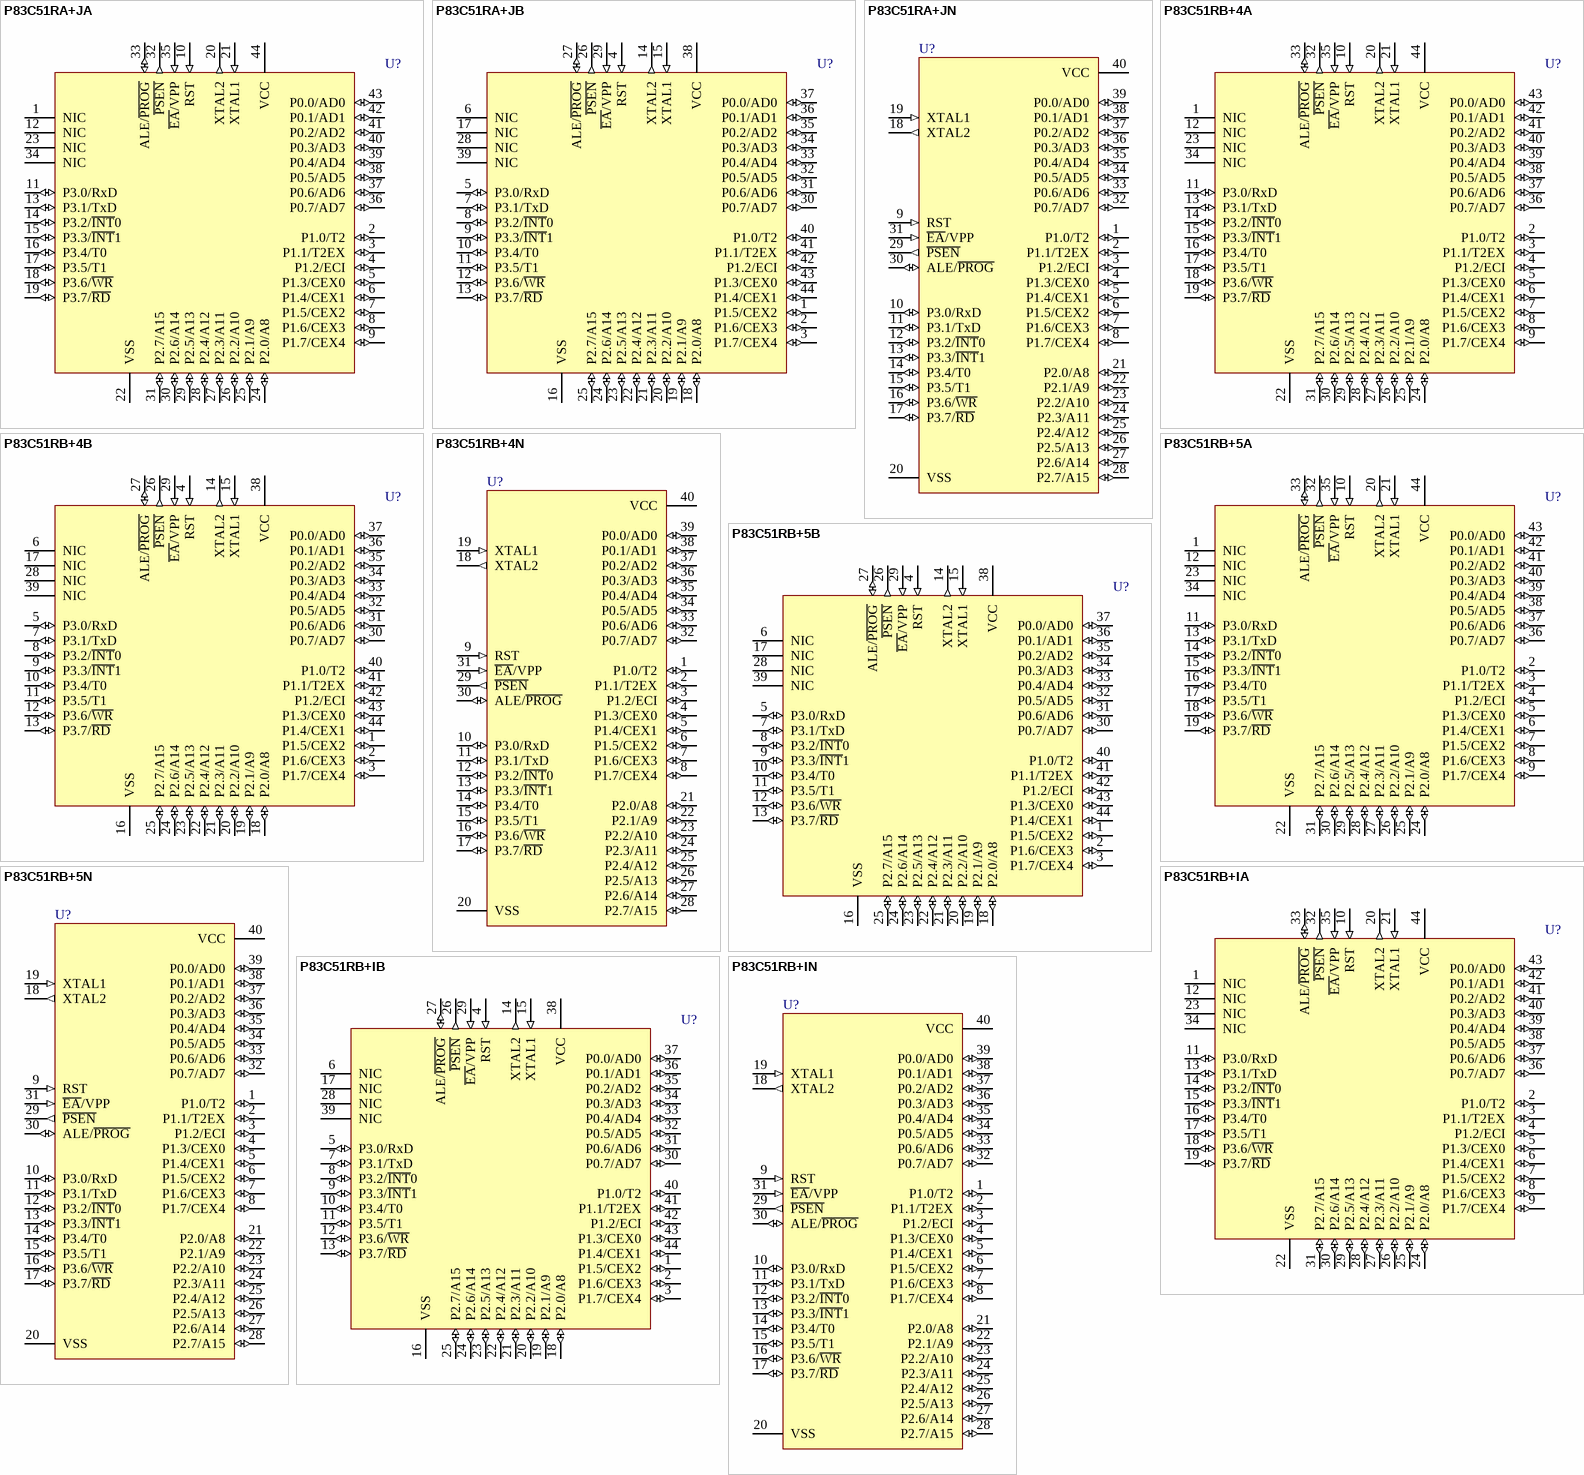
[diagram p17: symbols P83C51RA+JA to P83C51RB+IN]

## P83C51RA+JA
designator U?
80C51 8-Bit Microcontroller Family: 512 B RAM, 8 kB ROM, 5V, Low Power, High Speed
footprint SOT187-2_N (Leaded Chip Carrier, 44-Leads, Body 16.6x16.6mm, Pitch 1.27mm, IPC Medium Density)
footprint SOT187-2_L (Leaded Chip Carrier, 44-Leads, Body 16.6x16.6mm, Pitch 1.27mm, IPC High Density)
footprint SOT187-2_M (Leaded Chip Carrier, 44-Leads, Body 16.6x16.6mm, Pitch 1.27mm, IPC Low Density)
pins: 1 NIC, 2 P1.0/T2 (io), 3 P1.1/T2EX (io), 4 P1.2/ECI (io), 5 P1.3/CEX0 (io), 6 P1.4/CEX1 (io), 7 P1.5/CEX2 (io), 8 P1.6/CEX3 (io), 9 P1.7/CEX4 (io), 10 RST (in), 11 P3.0/RxD (io), 12 NIC, 13 P3.1/TxD (io), 14 P3.2/~{INT}0 (io), 15 P3.3/~{INT}1 (io), 16 P3.4/T0 (io), 17 P3.5/T1 (io), 18 P3.6/~{WR} (io), 19 P3.7/~{RD} (io), 20 XTAL2 (out), 21 XTAL1 (in), 22 VSS (power), 23 NIC, 24 P2.0/A8 (io), 25 P2.1/A9 (io), 26 P2.2/A10 (io), 27 P2.3/A11 (io), 28 P2.4/A12 (io), 29 P2.5/A13 (io), 30 P2.6/A14 (io), 31 P2.7/A15 (io), 32 ~{PSEN} (out), 33 ALE/~{PROG} (io), 34 NIC, 35 ~{EA}/VPP (in), 36 P0.7/AD7 (io), 37 P0.6/AD6 (io), 38 P0.5/AD5 (io), 39 P0.4/AD4 (io), 40 P0.3/AD3 (io), 41 P0.2/AD2 (io), 42 P0.1/AD1 (io), 43 P0.0/AD0 (io), 44 VCC (power)

## P83C51RA+JB
designator U?
80C51 8-Bit Microcontroller Family: 512 B RAM, 8 kB ROM, 5V, Low Power, High Speed
footprint SOT307-2_N (QFP, 44-Leads, Body 10x10mm, Pitch 0.8mm, IPC Medium Density)
footprint SOT307-2_L (QFP, 44-Leads, Body 10x10mm, Pitch 0.8mm, IPC High Density)
footprint SOT307-2_M (QFP, 44-Leads, Body 10x10mm, Pitch 0.8mm, IPC Low Density)
pins: 1 P1.5/CEX2 (io), 2 P1.6/CEX3 (io), 3 P1.7/CEX4 (io), 4 RST (in), 5 P3.0/RxD (io), 6 NIC, 7 P3.1/TxD (io), 8 P3.2/~{INT}0 (io), 9 P3.3/~{INT}1 (io), 10 P3.4/T0 (io), 11 P3.5/T1 (io), 12 P3.6/~{WR} (io), 13 P3.7/~{RD} (io), 14 XTAL2 (out), 15 XTAL1 (in), 16 VSS (power), 17 NIC, 18 P2.0/A8 (io), 19 P2.1/A9 (io), 20 P2.2/A10 (io), 21 P2.3/A11 (io), 22 P2.4/A12 (io), 23 P2.5/A13 (io), 24 P2.6/A14 (io), 25 P2.7/A15 (io), 26 ~{PSEN} (out), 27 ALE/~{PROG} (io), 28 NIC, 29 ~{EA}/VPP (in), 30 P0.7/AD7 (io), 31 P0.6/AD6 (io), 32 P0.5/AD5 (io), 33 P0.4/AD4 (io), 34 P0.3/AD3 (io), 35 P0.2/AD2 (io), 36 P0.1/AD1 (io), 37 P0.0/AD0 (io), 38 VCC (power), 39 NIC, 40 P1.0/T2 (io), 41 P1.1/T2EX (io), 42 P1.2/ECI (io), 43 P1.3/CEX0 (io), 44 P1.4/CEX1 (io)

## P83C51RA+JN
designator U?
80C51 8-Bit Microcontroller Family: 512 B RAM, 8 kB ROM, 5V, Low Power, High Speed
footprint SOT129-1 (DIP, Plastic; 40 Leads; Row Spacing 15.24 mm; Pitch 2.54 mm)
pins: 1 P1.0/T2 (io), 2 P1.1/T2EX (io), 3 P1.2/ECI (io), 4 P1.3/CEX0 (io), 5 P1.4/CEX1 (io), 6 P1.5/CEX2 (io), 7 P1.6/CEX3 (io), 8 P1.7/CEX4 (io), 9 RST (in), 10 P3.0/RxD (io), 11 P3.1/TxD (io), 12 P3.2/~{INT}0 (io), 13 P3.3/~{INT}1 (io), 14 P3.4/T0 (io), 15 P3.5/T1 (io), 16 P3.6/~{WR} (io), 17 P3.7/~{RD} (io), 18 XTAL2 (out), 19 XTAL1 (in), 20 VSS (power), 21 P2.0/A8 (io), 22 P2.1/A9 (io), 23 P2.2/A10 (io), 24 P2.3/A11 (io), 25 P2.4/A12 (io), 26 P2.5/A13 (io), 27 P2.6/A14 (io), 28 P2.7/A15 (io), 29 ~{PSEN} (out), 30 ALE/~{PROG} (io), 31 ~{EA}/VPP (in), 32 P0.7/AD7 (io), 33 P0.6/AD6 (io), 34 P0.5/AD5 (io), 35 P0.4/AD4 (io), 36 P0.3/AD3 (io), 37 P0.2/AD2 (io), 38 P0.1/AD1 (io), 39 P0.0/AD0 (io), 40 VCC (power)

## P83C51RB+4A
designator U?
80C51 8-Bit Microcontroller Family: 512 B RAM, 16 kB ROM, 2.7V-5.5V, Low Power, High Speed
footprint SOT187-2_N (Leaded Chip Carrier, 44-Leads, Body 16.6x16.6mm, Pitch 1.27mm, IPC Medium Density)
footprint SOT187-2_L (Leaded Chip Carrier, 44-Leads, Body 16.6x16.6mm, Pitch 1.27mm, IPC High Density)
footprint SOT187-2_M (Leaded Chip Carrier, 44-Leads, Body 16.6x16.6mm, Pitch 1.27mm, IPC Low Density)
pins: 1 NIC, 2 P1.0/T2 (io), 3 P1.1/T2EX (io), 4 P1.2/ECI (io), 5 P1.3/CEX0 (io), 6 P1.4/CEX1 (io), 7 P1.5/CEX2 (io), 8 P1.6/CEX3 (io), 9 P1.7/CEX4 (io), 10 RST (in), 11 P3.0/RxD (io), 12 NIC, 13 P3.1/TxD (io), 14 P3.2/~{INT}0 (io), 15 P3.3/~{INT}1 (io), 16 P3.4/T0 (io), 17 P3.5/T1 (io), 18 P3.6/~{WR} (io), 19 P3.7/~{RD} (io), 20 XTAL2 (out), 21 XTAL1 (in), 22 VSS (power), 23 NIC, 24 P2.0/A8 (io), 25 P2.1/A9 (io), 26 P2.2/A10 (io), 27 P2.3/A11 (io), 28 P2.4/A12 (io), 29 P2.5/A13 (io), 30 P2.6/A14 (io), 31 P2.7/A15 (io), 32 ~{PSEN} (out), 33 ALE/~{PROG} (io), 34 NIC, 35 ~{EA}/VPP (in), 36 P0.7/AD7 (io), 37 P0.6/AD6 (io), 38 P0.5/AD5 (io), 39 P0.4/AD4 (io), 40 P0.3/AD3 (io), 41 P0.2/AD2 (io), 42 P0.1/AD1 (io), 43 P0.0/AD0 (io), 44 VCC (power)

## P83C51RB+4B
designator U?
80C51 8-Bit Microcontroller Family: 512 B RAM, 16 kB ROM, 2.7V-5.5V, Low Power, High Speed
footprint SOT307-2_N (QFP, 44-Leads, Body 10x10mm, Pitch 0.8mm, IPC Medium Density)
footprint SOT307-2_L (QFP, 44-Leads, Body 10x10mm, Pitch 0.8mm, IPC High Density)
footprint SOT307-2_M (QFP, 44-Leads, Body 10x10mm, Pitch 0.8mm, IPC Low Density)
pins: 1 P1.5/CEX2 (io), 2 P1.6/CEX3 (io), 3 P1.7/CEX4 (io), 4 RST (in), 5 P3.0/RxD (io), 6 NIC, 7 P3.1/TxD (io), 8 P3.2/~{INT}0 (io), 9 P3.3/~{INT}1 (io), 10 P3.4/T0 (io), 11 P3.5/T1 (io), 12 P3.6/~{WR} (io), 13 P3.7/~{RD} (io), 14 XTAL2 (out), 15 XTAL1 (in), 16 VSS (power), 17 NIC, 18 P2.0/A8 (io), 19 P2.1/A9 (io), 20 P2.2/A10 (io), 21 P2.3/A11 (io), 22 P2.4/A12 (io), 23 P2.5/A13 (io), 24 P2.6/A14 (io), 25 P2.7/A15 (io), 26 ~{PSEN} (out), 27 ALE/~{PROG} (io), 28 NIC, 29 ~{EA}/VPP (in), 30 P0.7/AD7 (io), 31 P0.6/AD6 (io), 32 P0.5/AD5 (io), 33 P0.4/AD4 (io), 34 P0.3/AD3 (io), 35 P0.2/AD2 (io), 36 P0.1/AD1 (io), 37 P0.0/AD0 (io), 38 VCC (power), 39 NIC, 40 P1.0/T2 (io), 41 P1.1/T2EX (io), 42 P1.2/ECI (io), 43 P1.3/CEX0 (io), 44 P1.4/CEX1 (io)

## P83C51RB+4N
designator U?
80C51 8-Bit Microcontroller Family: 512 B RAM, 16 kB ROM, 2.7V-5.5V, Low Power, High Speed
footprint SOT129-1 (DIP, Plastic; 40 Leads; Row Spacing 15.24 mm; Pitch 2.54 mm)
pins: 1 P1.0/T2 (io), 2 P1.1/T2EX (io), 3 P1.2/ECI (io), 4 P1.3/CEX0 (io), 5 P1.4/CEX1 (io), 6 P1.5/CEX2 (io), 7 P1.6/CEX3 (io), 8 P1.7/CEX4 (io), 9 RST (in), 10 P3.0/RxD (io), 11 P3.1/TxD (io), 12 P3.2/~{INT}0 (io), 13 P3.3/~{INT}1 (io), 14 P3.4/T0 (io), 15 P3.5/T1 (io), 16 P3.6/~{WR} (io), 17 P3.7/~{RD} (io), 18 XTAL2 (out), 19 XTAL1 (in), 20 VSS (power), 21 P2.0/A8 (io), 22 P2.1/A9 (io), 23 P2.2/A10 (io), 24 P2.3/A11 (io), 25 P2.4/A12 (io), 26 P2.5/A13 (io), 27 P2.6/A14 (io), 28 P2.7/A15 (io), 29 ~{PSEN} (out), 30 ALE/~{PROG} (io), 31 ~{EA}/VPP (in), 32 P0.7/AD7 (io), 33 P0.6/AD6 (io), 34 P0.5/AD5 (io), 35 P0.4/AD4 (io), 36 P0.3/AD3 (io), 37 P0.2/AD2 (io), 38 P0.1/AD1 (io), 39 P0.0/AD0 (io), 40 VCC (power)

## P83C51RB+5A
designator U?
80C51 8-Bit Microcontroller Family: 512 B RAM, 16 kB ROM, 2.7V-5.5V, Low Power, High Speed
footprint SOT187-2_N (Leaded Chip Carrier, 44-Leads, Body 16.6x16.6mm, Pitch 1.27mm, IPC Medium Density)
footprint SOT187-2_L (Leaded Chip Carrier, 44-Leads, Body 16.6x16.6mm, Pitch 1.27mm, IPC High Density)
footprint SOT187-2_M (Leaded Chip Carrier, 44-Leads, Body 16.6x16.6mm, Pitch 1.27mm, IPC Low Density)
pins: 1 NIC, 2 P1.0/T2 (io), 3 P1.1/T2EX (io), 4 P1.2/ECI (io), 5 P1.3/CEX0 (io), 6 P1.4/CEX1 (io), 7 P1.5/CEX2 (io), 8 P1.6/CEX3 (io), 9 P1.7/CEX4 (io), 10 RST (in), 11 P3.0/RxD (io), 12 NIC, 13 P3.1/TxD (io), 14 P3.2/~{INT}0 (io), 15 P3.3/~{INT}1 (io), 16 P3.4/T0 (io), 17 P3.5/T1 (io), 18 P3.6/~{WR} (io), 19 P3.7/~{RD} (io), 20 XTAL2 (out), 21 XTAL1 (in), 22 VSS (power), 23 NIC, 24 P2.0/A8 (io), 25 P2.1/A9 (io), 26 P2.2/A10 (io), 27 P2.3/A11 (io), 28 P2.4/A12 (io), 29 P2.5/A13 (io), 30 P2.6/A14 (io), 31 P2.7/A15 (io), 32 ~{PSEN} (out), 33 ALE/~{PROG} (io), 34 NIC, 35 ~{EA}/VPP (in), 36 P0.7/AD7 (io), 37 P0.6/AD6 (io), 38 P0.5/AD5 (io), 39 P0.4/AD4 (io), 40 P0.3/AD3 (io), 41 P0.2/AD2 (io), 42 P0.1/AD1 (io), 43 P0.0/AD0 (io), 44 VCC (power)

## P83C51RB+5B
designator U?
80C51 8-Bit Microcontroller Family: 512 B RAM, 16 kB ROM, 2.7V-5.5V, Low Power, High Speed
footprint SOT307-2_N (QFP, 44-Leads, Body 10x10mm, Pitch 0.8mm, IPC Medium Density)
footprint SOT307-2_L (QFP, 44-Leads, Body 10x10mm, Pitch 0.8mm, IPC High Density)
footprint SOT307-2_M (QFP, 44-Leads, Body 10x10mm, Pitch 0.8mm, IPC Low Density)
pins: 1 P1.5/CEX2 (io), 2 P1.6/CEX3 (io), 3 P1.7/CEX4 (io), 4 RST (in), 5 P3.0/RxD (io), 6 NIC, 7 P3.1/TxD (io), 8 P3.2/~{INT}0 (io), 9 P3.3/~{INT}1 (io), 10 P3.4/T0 (io), 11 P3.5/T1 (io), 12 P3.6/~{WR} (io), 13 P3.7/~{RD} (io), 14 XTAL2 (out), 15 XTAL1 (in), 16 VSS (power), 17 NIC, 18 P2.0/A8 (io), 19 P2.1/A9 (io), 20 P2.2/A10 (io), 21 P2.3/A11 (io), 22 P2.4/A12 (io), 23 P2.5/A13 (io), 24 P2.6/A14 (io), 25 P2.7/A15 (io), 26 ~{PSEN} (out), 27 ALE/~{PROG} (io), 28 NIC, 29 ~{EA}/VPP (in), 30 P0.7/AD7 (io), 31 P0.6/AD6 (io), 32 P0.5/AD5 (io), 33 P0.4/AD4 (io), 34 P0.3/AD3 (io), 35 P0.2/AD2 (io), 36 P0.1/AD1 (io), 37 P0.0/AD0 (io), 38 VCC (power), 39 NIC, 40 P1.0/T2 (io), 41 P1.1/T2EX (io), 42 P1.2/ECI (io), 43 P1.3/CEX0 (io), 44 P1.4/CEX1 (io)

## P83C51RB+5N
designator U?
80C51 8-Bit Microcontroller Family: 512 B RAM, 16 kB ROM, 2.7V-5.5V, Low Power, High Speed
footprint SOT129-1 (DIP, Plastic; 40 Leads; Row Spacing 15.24 mm; Pitch 2.54 mm)
pins: 1 P1.0/T2 (io), 2 P1.1/T2EX (io), 3 P1.2/ECI (io), 4 P1.3/CEX0 (io), 5 P1.4/CEX1 (io), 6 P1.5/CEX2 (io), 7 P1.6/CEX3 (io), 8 P1.7/CEX4 (io), 9 RST (in), 10 P3.0/RxD (io), 11 P3.1/TxD (io), 12 P3.2/~{INT}0 (io), 13 P3.3/~{INT}1 (io), 14 P3.4/T0 (io), 15 P3.5/T1 (io), 16 P3.6/~{WR} (io), 17 P3.7/~{RD} (io), 18 XTAL2 (out), 19 XTAL1 (in), 20 VSS (power), 21 P2.0/A8 (io), 22 P2.1/A9 (io), 23 P2.2/A10 (io), 24 P2.3/A11 (io), 25 P2.4/A12 (io), 26 P2.5/A13 (io), 27 P2.6/A14 (io), 28 P2.7/A15 (io), 29 ~{PSEN} (out), 30 ALE/~{PROG} (io), 31 ~{EA}/VPP (in), 32 P0.7/AD7 (io), 33 P0.6/AD6 (io), 34 P0.5/AD5 (io), 35 P0.4/AD4 (io), 36 P0.3/AD3 (io), 37 P0.2/AD2 (io), 38 P0.1/AD1 (io), 39 P0.0/AD0 (io), 40 VCC (power)

## P83C51RB+IA
designator U?
80C51 8-Bit Microcontroller Family: 512 B RAM, 16 kB ROM, 5V, Low Power, High Speed
footprint SOT187-2_N (Leaded Chip Carrier, 44-Leads, Body 16.6x16.6mm, Pitch 1.27mm, IPC Medium Density)
footprint SOT187-2_L (Leaded Chip Carrier, 44-Leads, Body 16.6x16.6mm, Pitch 1.27mm, IPC High Density)
footprint SOT187-2_M (Leaded Chip Carrier, 44-Leads, Body 16.6x16.6mm, Pitch 1.27mm, IPC Low Density)
pins: 1 NIC, 2 P1.0/T2 (io), 3 P1.1/T2EX (io), 4 P1.2/ECI (io), 5 P1.3/CEX0 (io), 6 P1.4/CEX1 (io), 7 P1.5/CEX2 (io), 8 P1.6/CEX3 (io), 9 P1.7/CEX4 (io), 10 RST (in), 11 P3.0/RxD (io), 12 NIC, 13 P3.1/TxD (io), 14 P3.2/~{INT}0 (io), 15 P3.3/~{INT}1 (io), 16 P3.4/T0 (io), 17 P3.5/T1 (io), 18 P3.6/~{WR} (io), 19 P3.7/~{RD} (io), 20 XTAL2 (out), 21 XTAL1 (in), 22 VSS (power), 23 NIC, 24 P2.0/A8 (io), 25 P2.1/A9 (io), 26 P2.2/A10 (io), 27 P2.3/A11 (io), 28 P2.4/A12 (io), 29 P2.5/A13 (io), 30 P2.6/A14 (io), 31 P2.7/A15 (io), 32 ~{PSEN} (out), 33 ALE/~{PROG} (io), 34 NIC, 35 ~{EA}/VPP (in), 36 P0.7/AD7 (io), 37 P0.6/AD6 (io), 38 P0.5/AD5 (io), 39 P0.4/AD4 (io), 40 P0.3/AD3 (io), 41 P0.2/AD2 (io), 42 P0.1/AD1 (io), 43 P0.0/AD0 (io), 44 VCC (power)

## P83C51RB+IB
designator U?
80C51 8-Bit Microcontroller Family: 512 B RAM, 16 kB ROM, 5V, Low Power, High Speed
footprint SOT307-2_N (QFP, 44-Leads, Body 10x10mm, Pitch 0.8mm, IPC Medium Density)
footprint SOT307-2_L (QFP, 44-Leads, Body 10x10mm, Pitch 0.8mm, IPC High Density)
footprint SOT307-2_M (QFP, 44-Leads, Body 10x10mm, Pitch 0.8mm, IPC Low Density)
pins: 1 P1.5/CEX2 (io), 2 P1.6/CEX3 (io), 3 P1.7/CEX4 (io), 4 RST (in), 5 P3.0/RxD (io), 6 NIC, 7 P3.1/TxD (io), 8 P3.2/~{INT}0 (io), 9 P3.3/~{INT}1 (io), 10 P3.4/T0 (io), 11 P3.5/T1 (io), 12 P3.6/~{WR} (io), 13 P3.7/~{RD} (io), 14 XTAL2 (out), 15 XTAL1 (in), 16 VSS (power), 17 NIC, 18 P2.0/A8 (io), 19 P2.1/A9 (io), 20 P2.2/A10 (io), 21 P2.3/A11 (io), 22 P2.4/A12 (io), 23 P2.5/A13 (io), 24 P2.6/A14 (io), 25 P2.7/A15 (io), 26 ~{PSEN} (out), 27 ALE/~{PROG} (io), 28 NIC, 29 ~{EA}/VPP (in), 30 P0.7/AD7 (io), 31 P0.6/AD6 (io), 32 P0.5/AD5 (io), 33 P0.4/AD4 (io), 34 P0.3/AD3 (io), 35 P0.2/AD2 (io), 36 P0.1/AD1 (io), 37 P0.0/AD0 (io), 38 VCC (power), 39 NIC, 40 P1.0/T2 (io), 41 P1.1/T2EX (io), 42 P1.2/ECI (io), 43 P1.3/CEX0 (io), 44 P1.4/CEX1 (io)

## P83C51RB+IN
designator U?
80C51 8-Bit Microcontroller Family: 512 B RAM, 16 kB ROM, 5V, Low Power, High Speed
footprint SOT129-1 (DIP, Plastic; 40 Leads; Row Spacing 15.24 mm; Pitch 2.54 mm)
pins: 1 P1.0/T2 (io), 2 P1.1/T2EX (io), 3 P1.2/ECI (io), 4 P1.3/CEX0 (io), 5 P1.4/CEX1 (io), 6 P1.5/CEX2 (io), 7 P1.6/CEX3 (io), 8 P1.7/CEX4 (io), 9 RST (in), 10 P3.0/RxD (io), 11 P3.1/TxD (io), 12 P3.2/~{INT}0 (io), 13 P3.3/~{INT}1 (io), 14 P3.4/T0 (io), 15 P3.5/T1 (io), 16 P3.6/~{WR} (io), 17 P3.7/~{RD} (io), 18 XTAL2 (out), 19 XTAL1 (in), 20 VSS (power), 21 P2.0/A8 (io), 22 P2.1/A9 (io), 23 P2.2/A10 (io), 24 P2.3/A11 (io), 25 P2.4/A12 (io), 26 P2.5/A13 (io), 27 P2.6/A14 (io), 28 P2.7/A15 (io), 29 ~{PSEN} (out), 30 ALE/~{PROG} (io), 31 ~{EA}/VPP (in), 32 P0.7/AD7 (io), 33 P0.6/AD6 (io), 34 P0.5/AD5 (io), 35 P0.4/AD4 (io), 36 P0.3/AD3 (io), 37 P0.2/AD2 (io), 38 P0.1/AD1 (io), 39 P0.0/AD0 (io), 40 VCC (power)

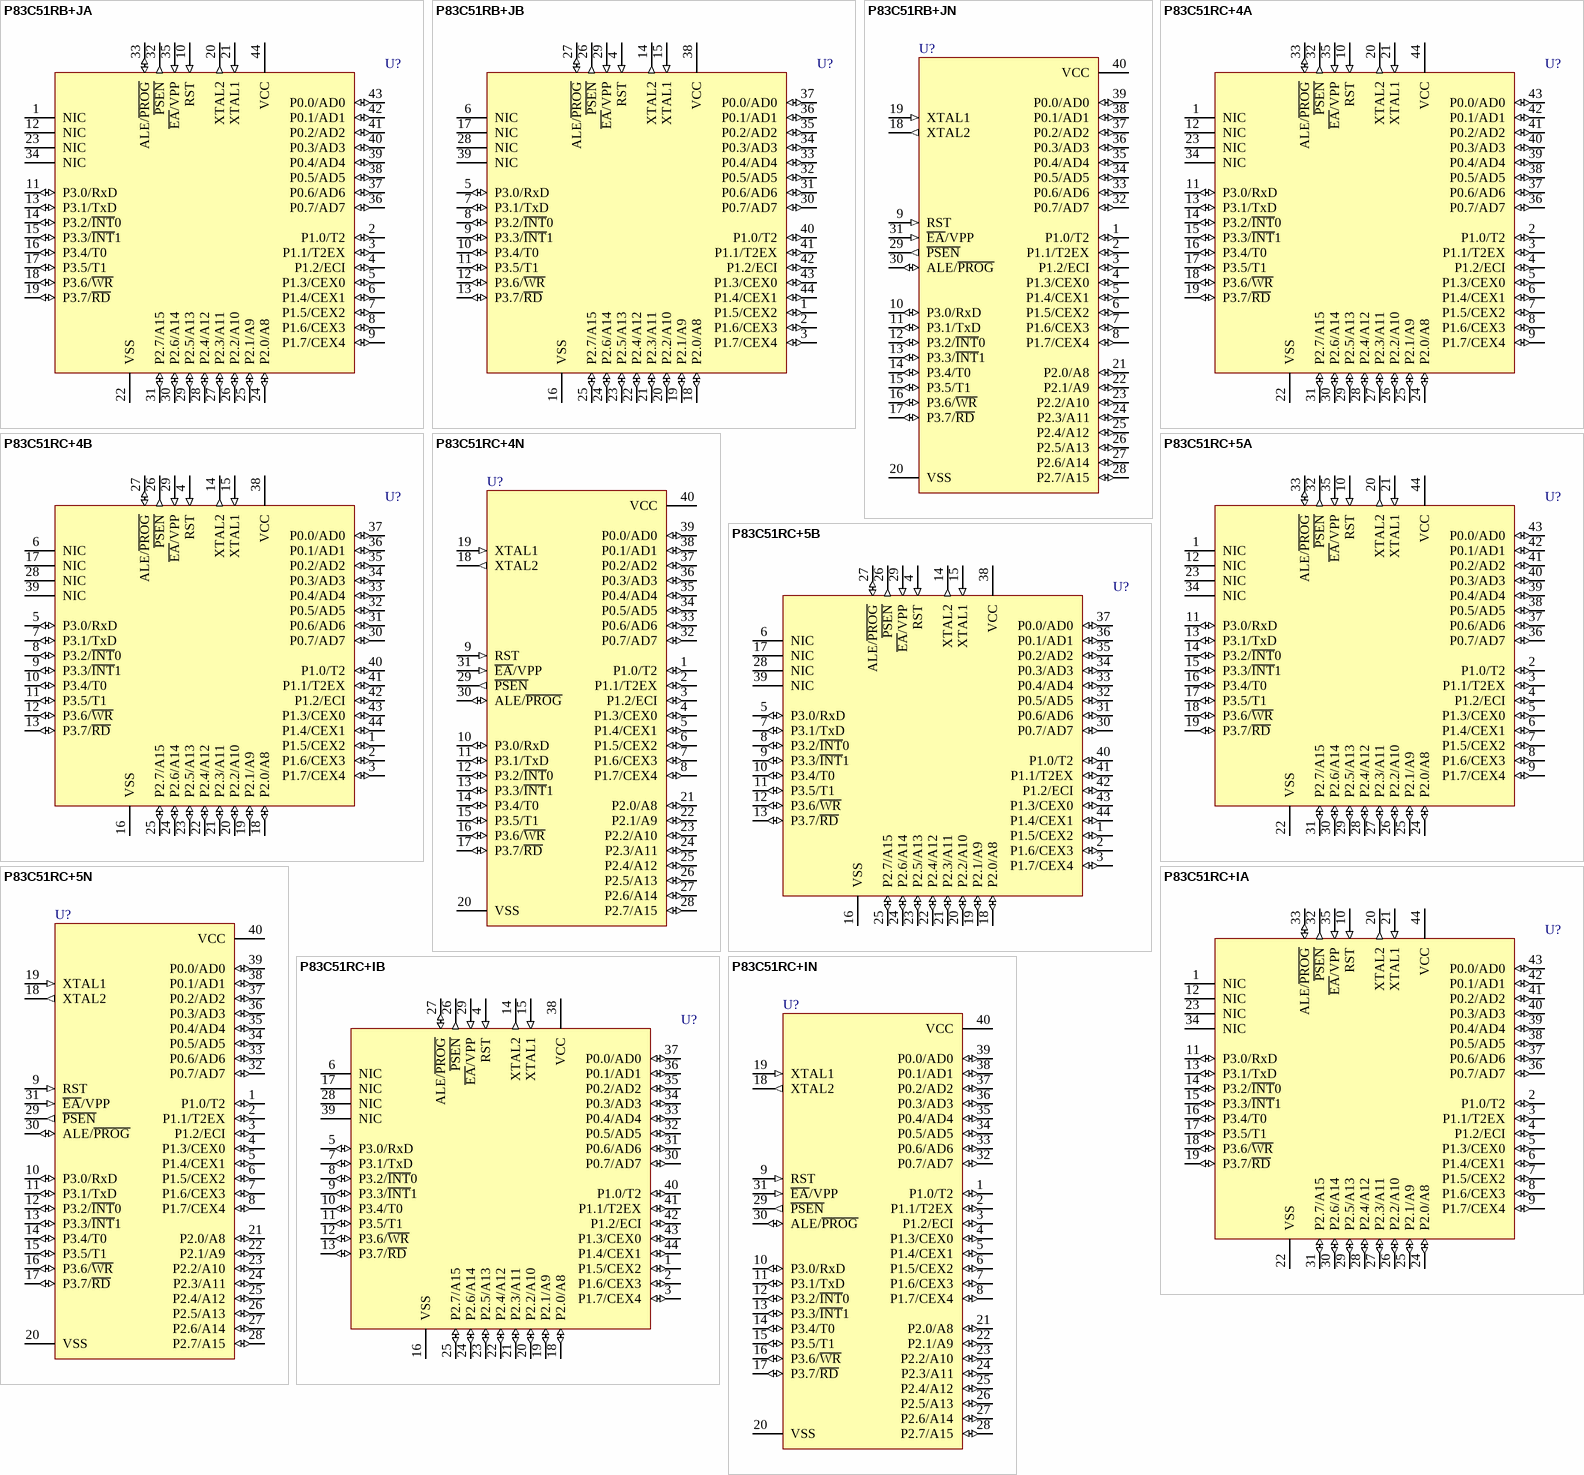
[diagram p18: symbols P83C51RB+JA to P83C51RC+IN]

## P83C51RB+JA
designator U?
80C51 8-Bit Microcontroller Family: 512 B RAM, 16 kB ROM, 5V, Low Power, High Speed
footprint SOT187-2_N (Leaded Chip Carrier, 44-Leads, Body 16.6x16.6mm, Pitch 1.27mm, IPC Medium Density)
footprint SOT187-2_L (Leaded Chip Carrier, 44-Leads, Body 16.6x16.6mm, Pitch 1.27mm, IPC High Density)
footprint SOT187-2_M (Leaded Chip Carrier, 44-Leads, Body 16.6x16.6mm, Pitch 1.27mm, IPC Low Density)
pins: 1 NIC, 2 P1.0/T2 (io), 3 P1.1/T2EX (io), 4 P1.2/ECI (io), 5 P1.3/CEX0 (io), 6 P1.4/CEX1 (io), 7 P1.5/CEX2 (io), 8 P1.6/CEX3 (io), 9 P1.7/CEX4 (io), 10 RST (in), 11 P3.0/RxD (io), 12 NIC, 13 P3.1/TxD (io), 14 P3.2/~{INT}0 (io), 15 P3.3/~{INT}1 (io), 16 P3.4/T0 (io), 17 P3.5/T1 (io), 18 P3.6/~{WR} (io), 19 P3.7/~{RD} (io), 20 XTAL2 (out), 21 XTAL1 (in), 22 VSS (power), 23 NIC, 24 P2.0/A8 (io), 25 P2.1/A9 (io), 26 P2.2/A10 (io), 27 P2.3/A11 (io), 28 P2.4/A12 (io), 29 P2.5/A13 (io), 30 P2.6/A14 (io), 31 P2.7/A15 (io), 32 ~{PSEN} (out), 33 ALE/~{PROG} (io), 34 NIC, 35 ~{EA}/VPP (in), 36 P0.7/AD7 (io), 37 P0.6/AD6 (io), 38 P0.5/AD5 (io), 39 P0.4/AD4 (io), 40 P0.3/AD3 (io), 41 P0.2/AD2 (io), 42 P0.1/AD1 (io), 43 P0.0/AD0 (io), 44 VCC (power)

## P83C51RB+JB
designator U?
80C51 8-Bit Microcontroller Family: 512 B RAM, 16 kB ROM, 5V, Low Power, High Speed
footprint SOT307-2_N (QFP, 44-Leads, Body 10x10mm, Pitch 0.8mm, IPC Medium Density)
footprint SOT307-2_L (QFP, 44-Leads, Body 10x10mm, Pitch 0.8mm, IPC High Density)
footprint SOT307-2_M (QFP, 44-Leads, Body 10x10mm, Pitch 0.8mm, IPC Low Density)
pins: 1 P1.5/CEX2 (io), 2 P1.6/CEX3 (io), 3 P1.7/CEX4 (io), 4 RST (in), 5 P3.0/RxD (io), 6 NIC, 7 P3.1/TxD (io), 8 P3.2/~{INT}0 (io), 9 P3.3/~{INT}1 (io), 10 P3.4/T0 (io), 11 P3.5/T1 (io), 12 P3.6/~{WR} (io), 13 P3.7/~{RD} (io), 14 XTAL2 (out), 15 XTAL1 (in), 16 VSS (power), 17 NIC, 18 P2.0/A8 (io), 19 P2.1/A9 (io), 20 P2.2/A10 (io), 21 P2.3/A11 (io), 22 P2.4/A12 (io), 23 P2.5/A13 (io), 24 P2.6/A14 (io), 25 P2.7/A15 (io), 26 ~{PSEN} (out), 27 ALE/~{PROG} (io), 28 NIC, 29 ~{EA}/VPP (in), 30 P0.7/AD7 (io), 31 P0.6/AD6 (io), 32 P0.5/AD5 (io), 33 P0.4/AD4 (io), 34 P0.3/AD3 (io), 35 P0.2/AD2 (io), 36 P0.1/AD1 (io), 37 P0.0/AD0 (io), 38 VCC (power), 39 NIC, 40 P1.0/T2 (io), 41 P1.1/T2EX (io), 42 P1.2/ECI (io), 43 P1.3/CEX0 (io), 44 P1.4/CEX1 (io)

## P83C51RB+JN
designator U?
80C51 8-Bit Microcontroller Family: 512 B RAM, 16 kB ROM, 5V, Low Power, High Speed
footprint SOT129-1 (DIP, Plastic; 40 Leads; Row Spacing 15.24 mm; Pitch 2.54 mm)
pins: 1 P1.0/T2 (io), 2 P1.1/T2EX (io), 3 P1.2/ECI (io), 4 P1.3/CEX0 (io), 5 P1.4/CEX1 (io), 6 P1.5/CEX2 (io), 7 P1.6/CEX3 (io), 8 P1.7/CEX4 (io), 9 RST (in), 10 P3.0/RxD (io), 11 P3.1/TxD (io), 12 P3.2/~{INT}0 (io), 13 P3.3/~{INT}1 (io), 14 P3.4/T0 (io), 15 P3.5/T1 (io), 16 P3.6/~{WR} (io), 17 P3.7/~{RD} (io), 18 XTAL2 (out), 19 XTAL1 (in), 20 VSS (power), 21 P2.0/A8 (io), 22 P2.1/A9 (io), 23 P2.2/A10 (io), 24 P2.3/A11 (io), 25 P2.4/A12 (io), 26 P2.5/A13 (io), 27 P2.6/A14 (io), 28 P2.7/A15 (io), 29 ~{PSEN} (out), 30 ALE/~{PROG} (io), 31 ~{EA}/VPP (in), 32 P0.7/AD7 (io), 33 P0.6/AD6 (io), 34 P0.5/AD5 (io), 35 P0.4/AD4 (io), 36 P0.3/AD3 (io), 37 P0.2/AD2 (io), 38 P0.1/AD1 (io), 39 P0.0/AD0 (io), 40 VCC (power)

## P83C51RC+4A
designator U?
80C51 8-Bit Microcontroller Family: 512 B RAM, 32 kB ROM, 2.7V-5.5V, Low Power, High Speed
footprint SOT187-2_N (Leaded Chip Carrier, 44-Leads, Body 16.6x16.6mm, Pitch 1.27mm, IPC Medium Density)
footprint SOT187-2_L (Leaded Chip Carrier, 44-Leads, Body 16.6x16.6mm, Pitch 1.27mm, IPC High Density)
footprint SOT187-2_M (Leaded Chip Carrier, 44-Leads, Body 16.6x16.6mm, Pitch 1.27mm, IPC Low Density)
pins: 1 NIC, 2 P1.0/T2 (io), 3 P1.1/T2EX (io), 4 P1.2/ECI (io), 5 P1.3/CEX0 (io), 6 P1.4/CEX1 (io), 7 P1.5/CEX2 (io), 8 P1.6/CEX3 (io), 9 P1.7/CEX4 (io), 10 RST (in), 11 P3.0/RxD (io), 12 NIC, 13 P3.1/TxD (io), 14 P3.2/~{INT}0 (io), 15 P3.3/~{INT}1 (io), 16 P3.4/T0 (io), 17 P3.5/T1 (io), 18 P3.6/~{WR} (io), 19 P3.7/~{RD} (io), 20 XTAL2 (out), 21 XTAL1 (in), 22 VSS (power), 23 NIC, 24 P2.0/A8 (io), 25 P2.1/A9 (io), 26 P2.2/A10 (io), 27 P2.3/A11 (io), 28 P2.4/A12 (io), 29 P2.5/A13 (io), 30 P2.6/A14 (io), 31 P2.7/A15 (io), 32 ~{PSEN} (out), 33 ALE/~{PROG} (io), 34 NIC, 35 ~{EA}/VPP (in), 36 P0.7/AD7 (io), 37 P0.6/AD6 (io), 38 P0.5/AD5 (io), 39 P0.4/AD4 (io), 40 P0.3/AD3 (io), 41 P0.2/AD2 (io), 42 P0.1/AD1 (io), 43 P0.0/AD0 (io), 44 VCC (power)

## P83C51RC+4B
designator U?
80C51 8-Bit Microcontroller Family: 512 B RAM, 32 kB ROM, 2.7V-5.5V, Low Power, High Speed
footprint SOT307-2_N (QFP, 44-Leads, Body 10x10mm, Pitch 0.8mm, IPC Medium Density)
footprint SOT307-2_L (QFP, 44-Leads, Body 10x10mm, Pitch 0.8mm, IPC High Density)
footprint SOT307-2_M (QFP, 44-Leads, Body 10x10mm, Pitch 0.8mm, IPC Low Density)
pins: 1 P1.5/CEX2 (io), 2 P1.6/CEX3 (io), 3 P1.7/CEX4 (io), 4 RST (in), 5 P3.0/RxD (io), 6 NIC, 7 P3.1/TxD (io), 8 P3.2/~{INT}0 (io), 9 P3.3/~{INT}1 (io), 10 P3.4/T0 (io), 11 P3.5/T1 (io), 12 P3.6/~{WR} (io), 13 P3.7/~{RD} (io), 14 XTAL2 (out), 15 XTAL1 (in), 16 VSS (power), 17 NIC, 18 P2.0/A8 (io), 19 P2.1/A9 (io), 20 P2.2/A10 (io), 21 P2.3/A11 (io), 22 P2.4/A12 (io), 23 P2.5/A13 (io), 24 P2.6/A14 (io), 25 P2.7/A15 (io), 26 ~{PSEN} (out), 27 ALE/~{PROG} (io), 28 NIC, 29 ~{EA}/VPP (in), 30 P0.7/AD7 (io), 31 P0.6/AD6 (io), 32 P0.5/AD5 (io), 33 P0.4/AD4 (io), 34 P0.3/AD3 (io), 35 P0.2/AD2 (io), 36 P0.1/AD1 (io), 37 P0.0/AD0 (io), 38 VCC (power), 39 NIC, 40 P1.0/T2 (io), 41 P1.1/T2EX (io), 42 P1.2/ECI (io), 43 P1.3/CEX0 (io), 44 P1.4/CEX1 (io)

## P83C51RC+4N
designator U?
80C51 8-Bit Microcontroller Family: 512 B RAM, 32 kB ROM, 2.7V-5.5V, Low Power, High Speed
footprint SOT129-1 (DIP, Plastic; 40 Leads; Row Spacing 15.24 mm; Pitch 2.54 mm)
pins: 1 P1.0/T2 (io), 2 P1.1/T2EX (io), 3 P1.2/ECI (io), 4 P1.3/CEX0 (io), 5 P1.4/CEX1 (io), 6 P1.5/CEX2 (io), 7 P1.6/CEX3 (io), 8 P1.7/CEX4 (io), 9 RST (in), 10 P3.0/RxD (io), 11 P3.1/TxD (io), 12 P3.2/~{INT}0 (io), 13 P3.3/~{INT}1 (io), 14 P3.4/T0 (io), 15 P3.5/T1 (io), 16 P3.6/~{WR} (io), 17 P3.7/~{RD} (io), 18 XTAL2 (out), 19 XTAL1 (in), 20 VSS (power), 21 P2.0/A8 (io), 22 P2.1/A9 (io), 23 P2.2/A10 (io), 24 P2.3/A11 (io), 25 P2.4/A12 (io), 26 P2.5/A13 (io), 27 P2.6/A14 (io), 28 P2.7/A15 (io), 29 ~{PSEN} (out), 30 ALE/~{PROG} (io), 31 ~{EA}/VPP (in), 32 P0.7/AD7 (io), 33 P0.6/AD6 (io), 34 P0.5/AD5 (io), 35 P0.4/AD4 (io), 36 P0.3/AD3 (io), 37 P0.2/AD2 (io), 38 P0.1/AD1 (io), 39 P0.0/AD0 (io), 40 VCC (power)

## P83C51RC+5A
designator U?
80C51 8-Bit Microcontroller Family: 512 B RAM, 32 kB ROM, 2.7V-5.5V, Low Power, High Speed
footprint SOT187-2_N (Leaded Chip Carrier, 44-Leads, Body 16.6x16.6mm, Pitch 1.27mm, IPC Medium Density)
footprint SOT187-2_L (Leaded Chip Carrier, 44-Leads, Body 16.6x16.6mm, Pitch 1.27mm, IPC High Density)
footprint SOT187-2_M (Leaded Chip Carrier, 44-Leads, Body 16.6x16.6mm, Pitch 1.27mm, IPC Low Density)
pins: 1 NIC, 2 P1.0/T2 (io), 3 P1.1/T2EX (io), 4 P1.2/ECI (io), 5 P1.3/CEX0 (io), 6 P1.4/CEX1 (io), 7 P1.5/CEX2 (io), 8 P1.6/CEX3 (io), 9 P1.7/CEX4 (io), 10 RST (in), 11 P3.0/RxD (io), 12 NIC, 13 P3.1/TxD (io), 14 P3.2/~{INT}0 (io), 15 P3.3/~{INT}1 (io), 16 P3.4/T0 (io), 17 P3.5/T1 (io), 18 P3.6/~{WR} (io), 19 P3.7/~{RD} (io), 20 XTAL2 (out), 21 XTAL1 (in), 22 VSS (power), 23 NIC, 24 P2.0/A8 (io), 25 P2.1/A9 (io), 26 P2.2/A10 (io), 27 P2.3/A11 (io), 28 P2.4/A12 (io), 29 P2.5/A13 (io), 30 P2.6/A14 (io), 31 P2.7/A15 (io), 32 ~{PSEN} (out), 33 ALE/~{PROG} (io), 34 NIC, 35 ~{EA}/VPP (in), 36 P0.7/AD7 (io), 37 P0.6/AD6 (io), 38 P0.5/AD5 (io), 39 P0.4/AD4 (io), 40 P0.3/AD3 (io), 41 P0.2/AD2 (io), 42 P0.1/AD1 (io), 43 P0.0/AD0 (io), 44 VCC (power)

## P83C51RC+5B
designator U?
80C51 8-Bit Microcontroller Family: 512 B RAM, 32 kB ROM, 2.7V-5.5V, Low Power, High Speed
footprint SOT307-2_N (QFP, 44-Leads, Body 10x10mm, Pitch 0.8mm, IPC Medium Density)
footprint SOT307-2_L (QFP, 44-Leads, Body 10x10mm, Pitch 0.8mm, IPC High Density)
footprint SOT307-2_M (QFP, 44-Leads, Body 10x10mm, Pitch 0.8mm, IPC Low Density)
pins: 1 P1.5/CEX2 (io), 2 P1.6/CEX3 (io), 3 P1.7/CEX4 (io), 4 RST (in), 5 P3.0/RxD (io), 6 NIC, 7 P3.1/TxD (io), 8 P3.2/~{INT}0 (io), 9 P3.3/~{INT}1 (io), 10 P3.4/T0 (io), 11 P3.5/T1 (io), 12 P3.6/~{WR} (io), 13 P3.7/~{RD} (io), 14 XTAL2 (out), 15 XTAL1 (in), 16 VSS (power), 17 NIC, 18 P2.0/A8 (io), 19 P2.1/A9 (io), 20 P2.2/A10 (io), 21 P2.3/A11 (io), 22 P2.4/A12 (io), 23 P2.5/A13 (io), 24 P2.6/A14 (io), 25 P2.7/A15 (io), 26 ~{PSEN} (out), 27 ALE/~{PROG} (io), 28 NIC, 29 ~{EA}/VPP (in), 30 P0.7/AD7 (io), 31 P0.6/AD6 (io), 32 P0.5/AD5 (io), 33 P0.4/AD4 (io), 34 P0.3/AD3 (io), 35 P0.2/AD2 (io), 36 P0.1/AD1 (io), 37 P0.0/AD0 (io), 38 VCC (power), 39 NIC, 40 P1.0/T2 (io), 41 P1.1/T2EX (io), 42 P1.2/ECI (io), 43 P1.3/CEX0 (io), 44 P1.4/CEX1 (io)

## P83C51RC+5N
designator U?
80C51 8-Bit Microcontroller Family: 512 B RAM, 32 kB ROM, 2.7V-5.5V, Low Power, High Speed
footprint SOT129-1 (DIP, Plastic; 40 Leads; Row Spacing 15.24 mm; Pitch 2.54 mm)
pins: 1 P1.0/T2 (io), 2 P1.1/T2EX (io), 3 P1.2/ECI (io), 4 P1.3/CEX0 (io), 5 P1.4/CEX1 (io), 6 P1.5/CEX2 (io), 7 P1.6/CEX3 (io), 8 P1.7/CEX4 (io), 9 RST (in), 10 P3.0/RxD (io), 11 P3.1/TxD (io), 12 P3.2/~{INT}0 (io), 13 P3.3/~{INT}1 (io), 14 P3.4/T0 (io), 15 P3.5/T1 (io), 16 P3.6/~{WR} (io), 17 P3.7/~{RD} (io), 18 XTAL2 (out), 19 XTAL1 (in), 20 VSS (power), 21 P2.0/A8 (io), 22 P2.1/A9 (io), 23 P2.2/A10 (io), 24 P2.3/A11 (io), 25 P2.4/A12 (io), 26 P2.5/A13 (io), 27 P2.6/A14 (io), 28 P2.7/A15 (io), 29 ~{PSEN} (out), 30 ALE/~{PROG} (io), 31 ~{EA}/VPP (in), 32 P0.7/AD7 (io), 33 P0.6/AD6 (io), 34 P0.5/AD5 (io), 35 P0.4/AD4 (io), 36 P0.3/AD3 (io), 37 P0.2/AD2 (io), 38 P0.1/AD1 (io), 39 P0.0/AD0 (io), 40 VCC (power)

## P83C51RC+IA
designator U?
80C51 8-Bit Microcontroller Family: 512 B RAM, 32 kB ROM, 5V, Low Power, High Speed
footprint SOT187-2_N (Leaded Chip Carrier, 44-Leads, Body 16.6x16.6mm, Pitch 1.27mm, IPC Medium Density)
footprint SOT187-2_L (Leaded Chip Carrier, 44-Leads, Body 16.6x16.6mm, Pitch 1.27mm, IPC High Density)
footprint SOT187-2_M (Leaded Chip Carrier, 44-Leads, Body 16.6x16.6mm, Pitch 1.27mm, IPC Low Density)
pins: 1 NIC, 2 P1.0/T2 (io), 3 P1.1/T2EX (io), 4 P1.2/ECI (io), 5 P1.3/CEX0 (io), 6 P1.4/CEX1 (io), 7 P1.5/CEX2 (io), 8 P1.6/CEX3 (io), 9 P1.7/CEX4 (io), 10 RST (in), 11 P3.0/RxD (io), 12 NIC, 13 P3.1/TxD (io), 14 P3.2/~{INT}0 (io), 15 P3.3/~{INT}1 (io), 16 P3.4/T0 (io), 17 P3.5/T1 (io), 18 P3.6/~{WR} (io), 19 P3.7/~{RD} (io), 20 XTAL2 (out), 21 XTAL1 (in), 22 VSS (power), 23 NIC, 24 P2.0/A8 (io), 25 P2.1/A9 (io), 26 P2.2/A10 (io), 27 P2.3/A11 (io), 28 P2.4/A12 (io), 29 P2.5/A13 (io), 30 P2.6/A14 (io), 31 P2.7/A15 (io), 32 ~{PSEN} (out), 33 ALE/~{PROG} (io), 34 NIC, 35 ~{EA}/VPP (in), 36 P0.7/AD7 (io), 37 P0.6/AD6 (io), 38 P0.5/AD5 (io), 39 P0.4/AD4 (io), 40 P0.3/AD3 (io), 41 P0.2/AD2 (io), 42 P0.1/AD1 (io), 43 P0.0/AD0 (io), 44 VCC (power)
